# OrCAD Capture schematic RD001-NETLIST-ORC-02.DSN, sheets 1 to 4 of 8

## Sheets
1 8: size A3
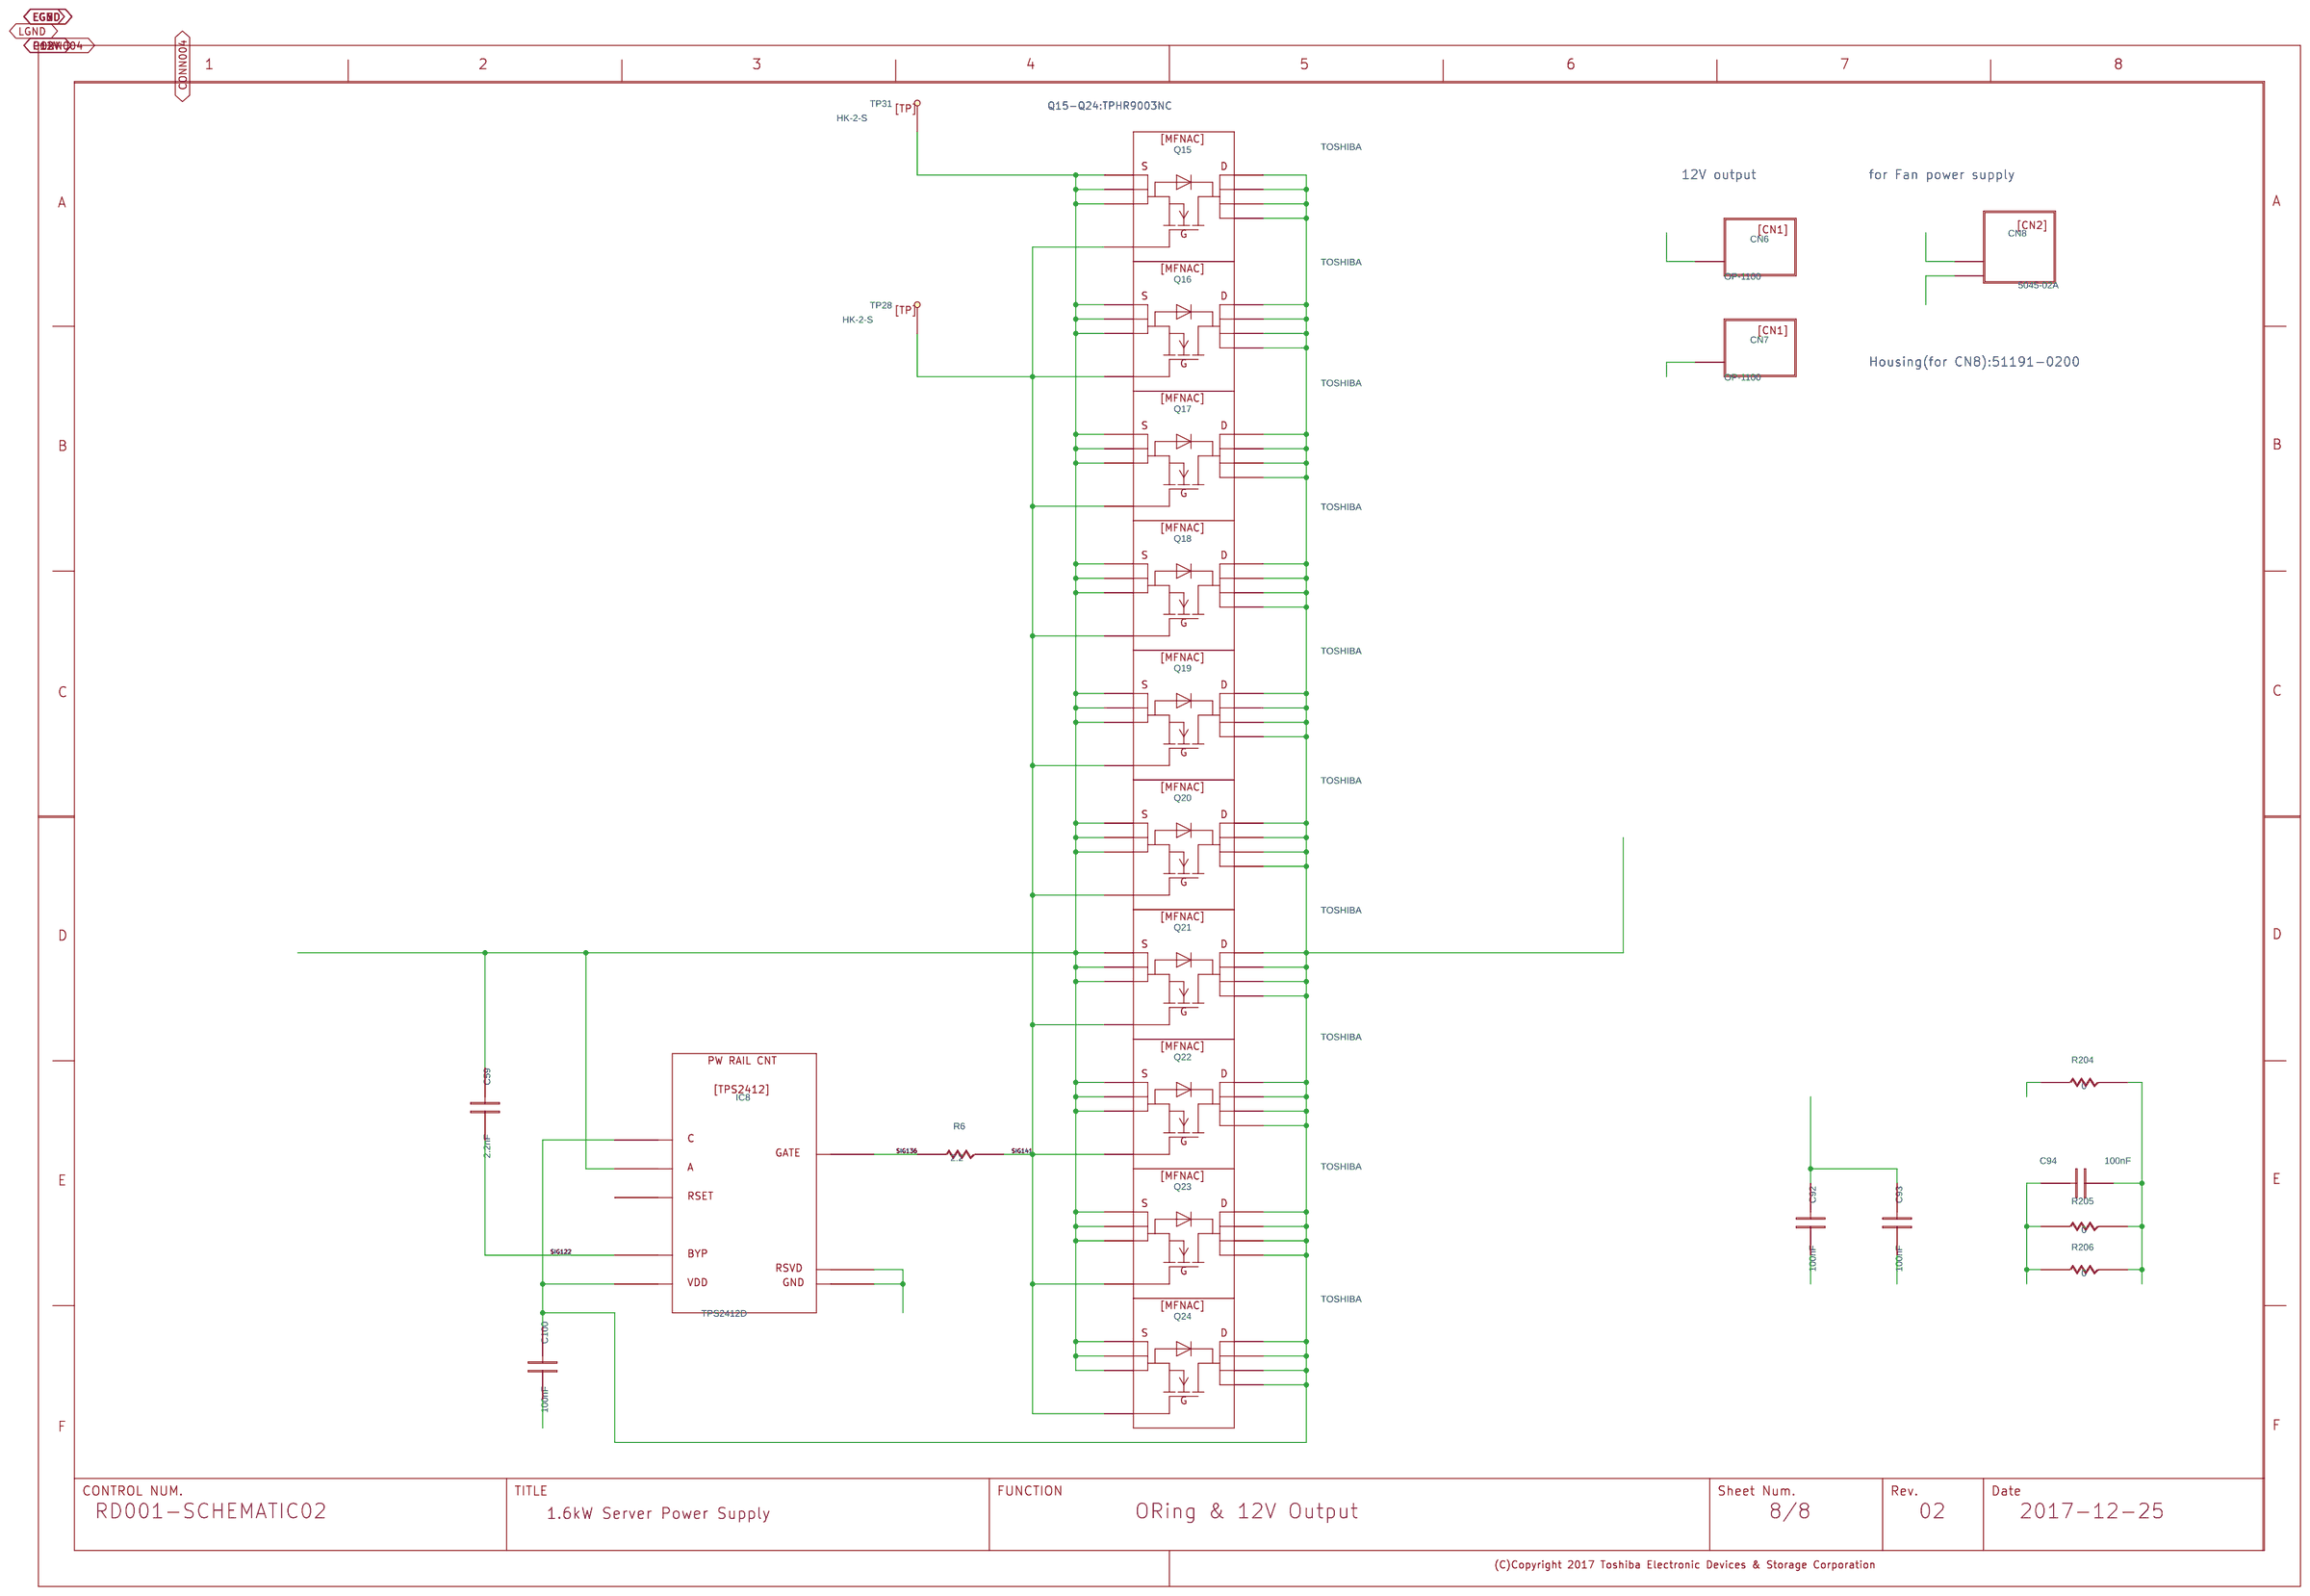
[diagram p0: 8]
2 7: size A3
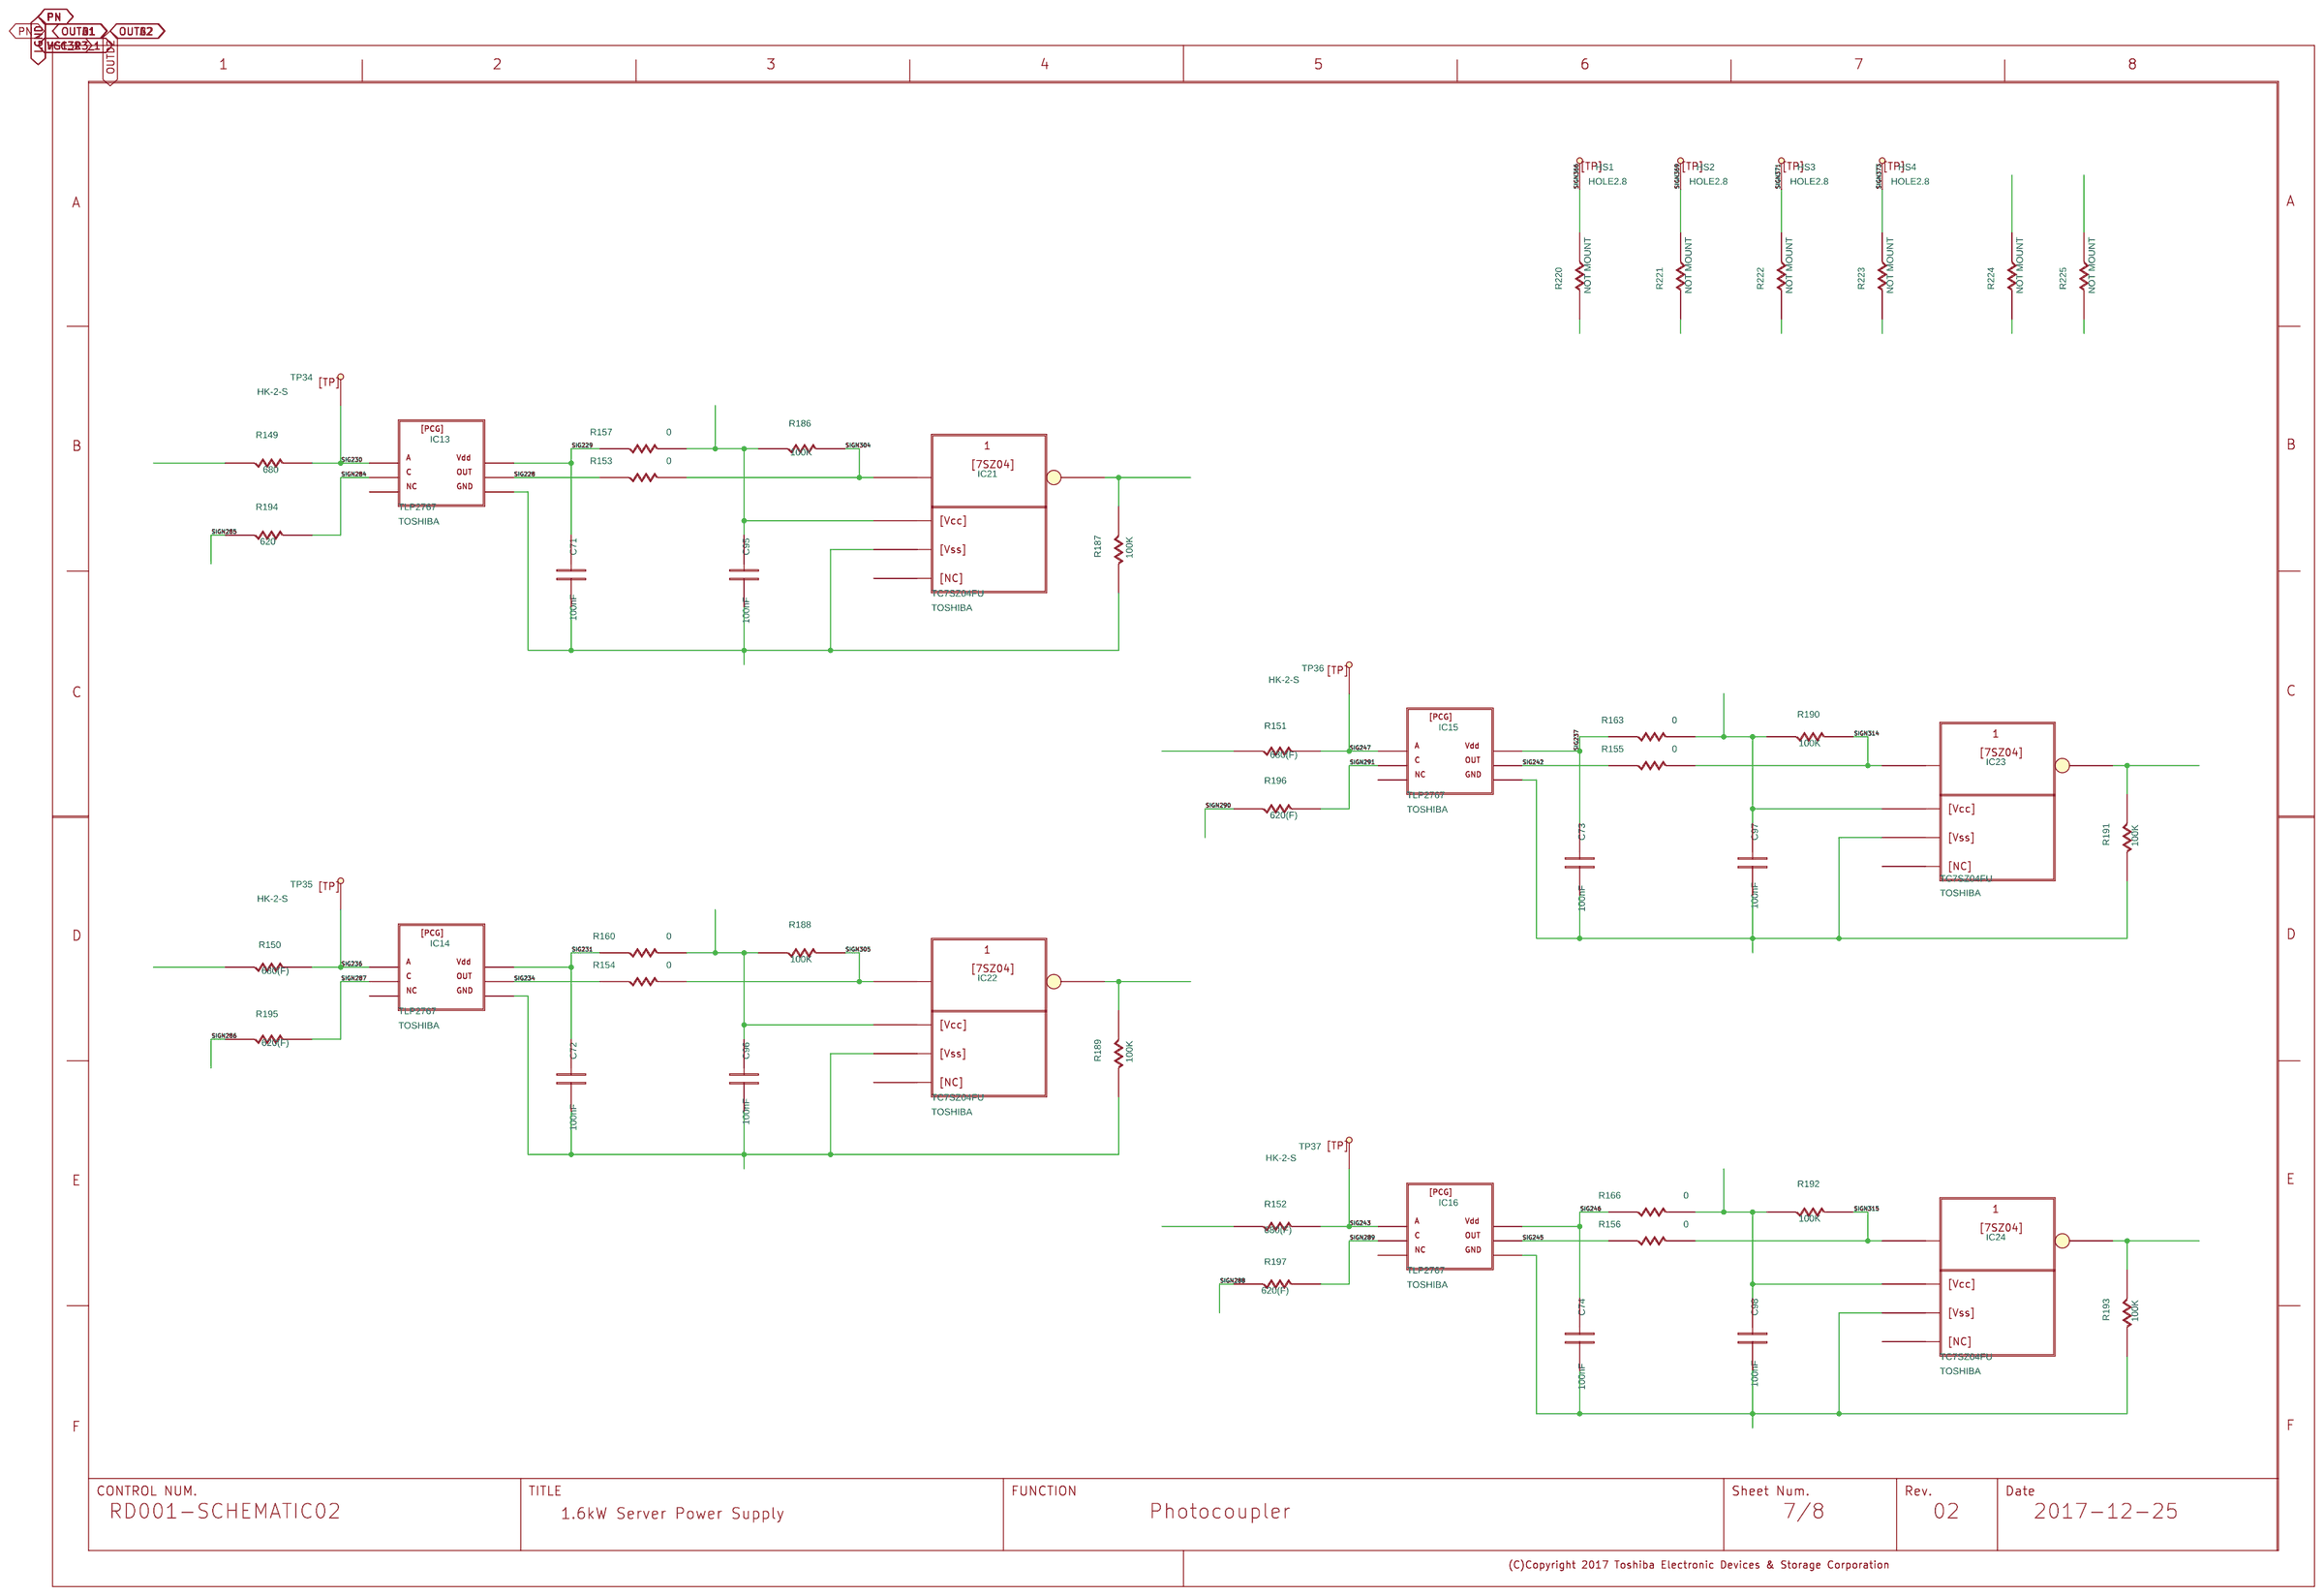
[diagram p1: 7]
3 6: size A3
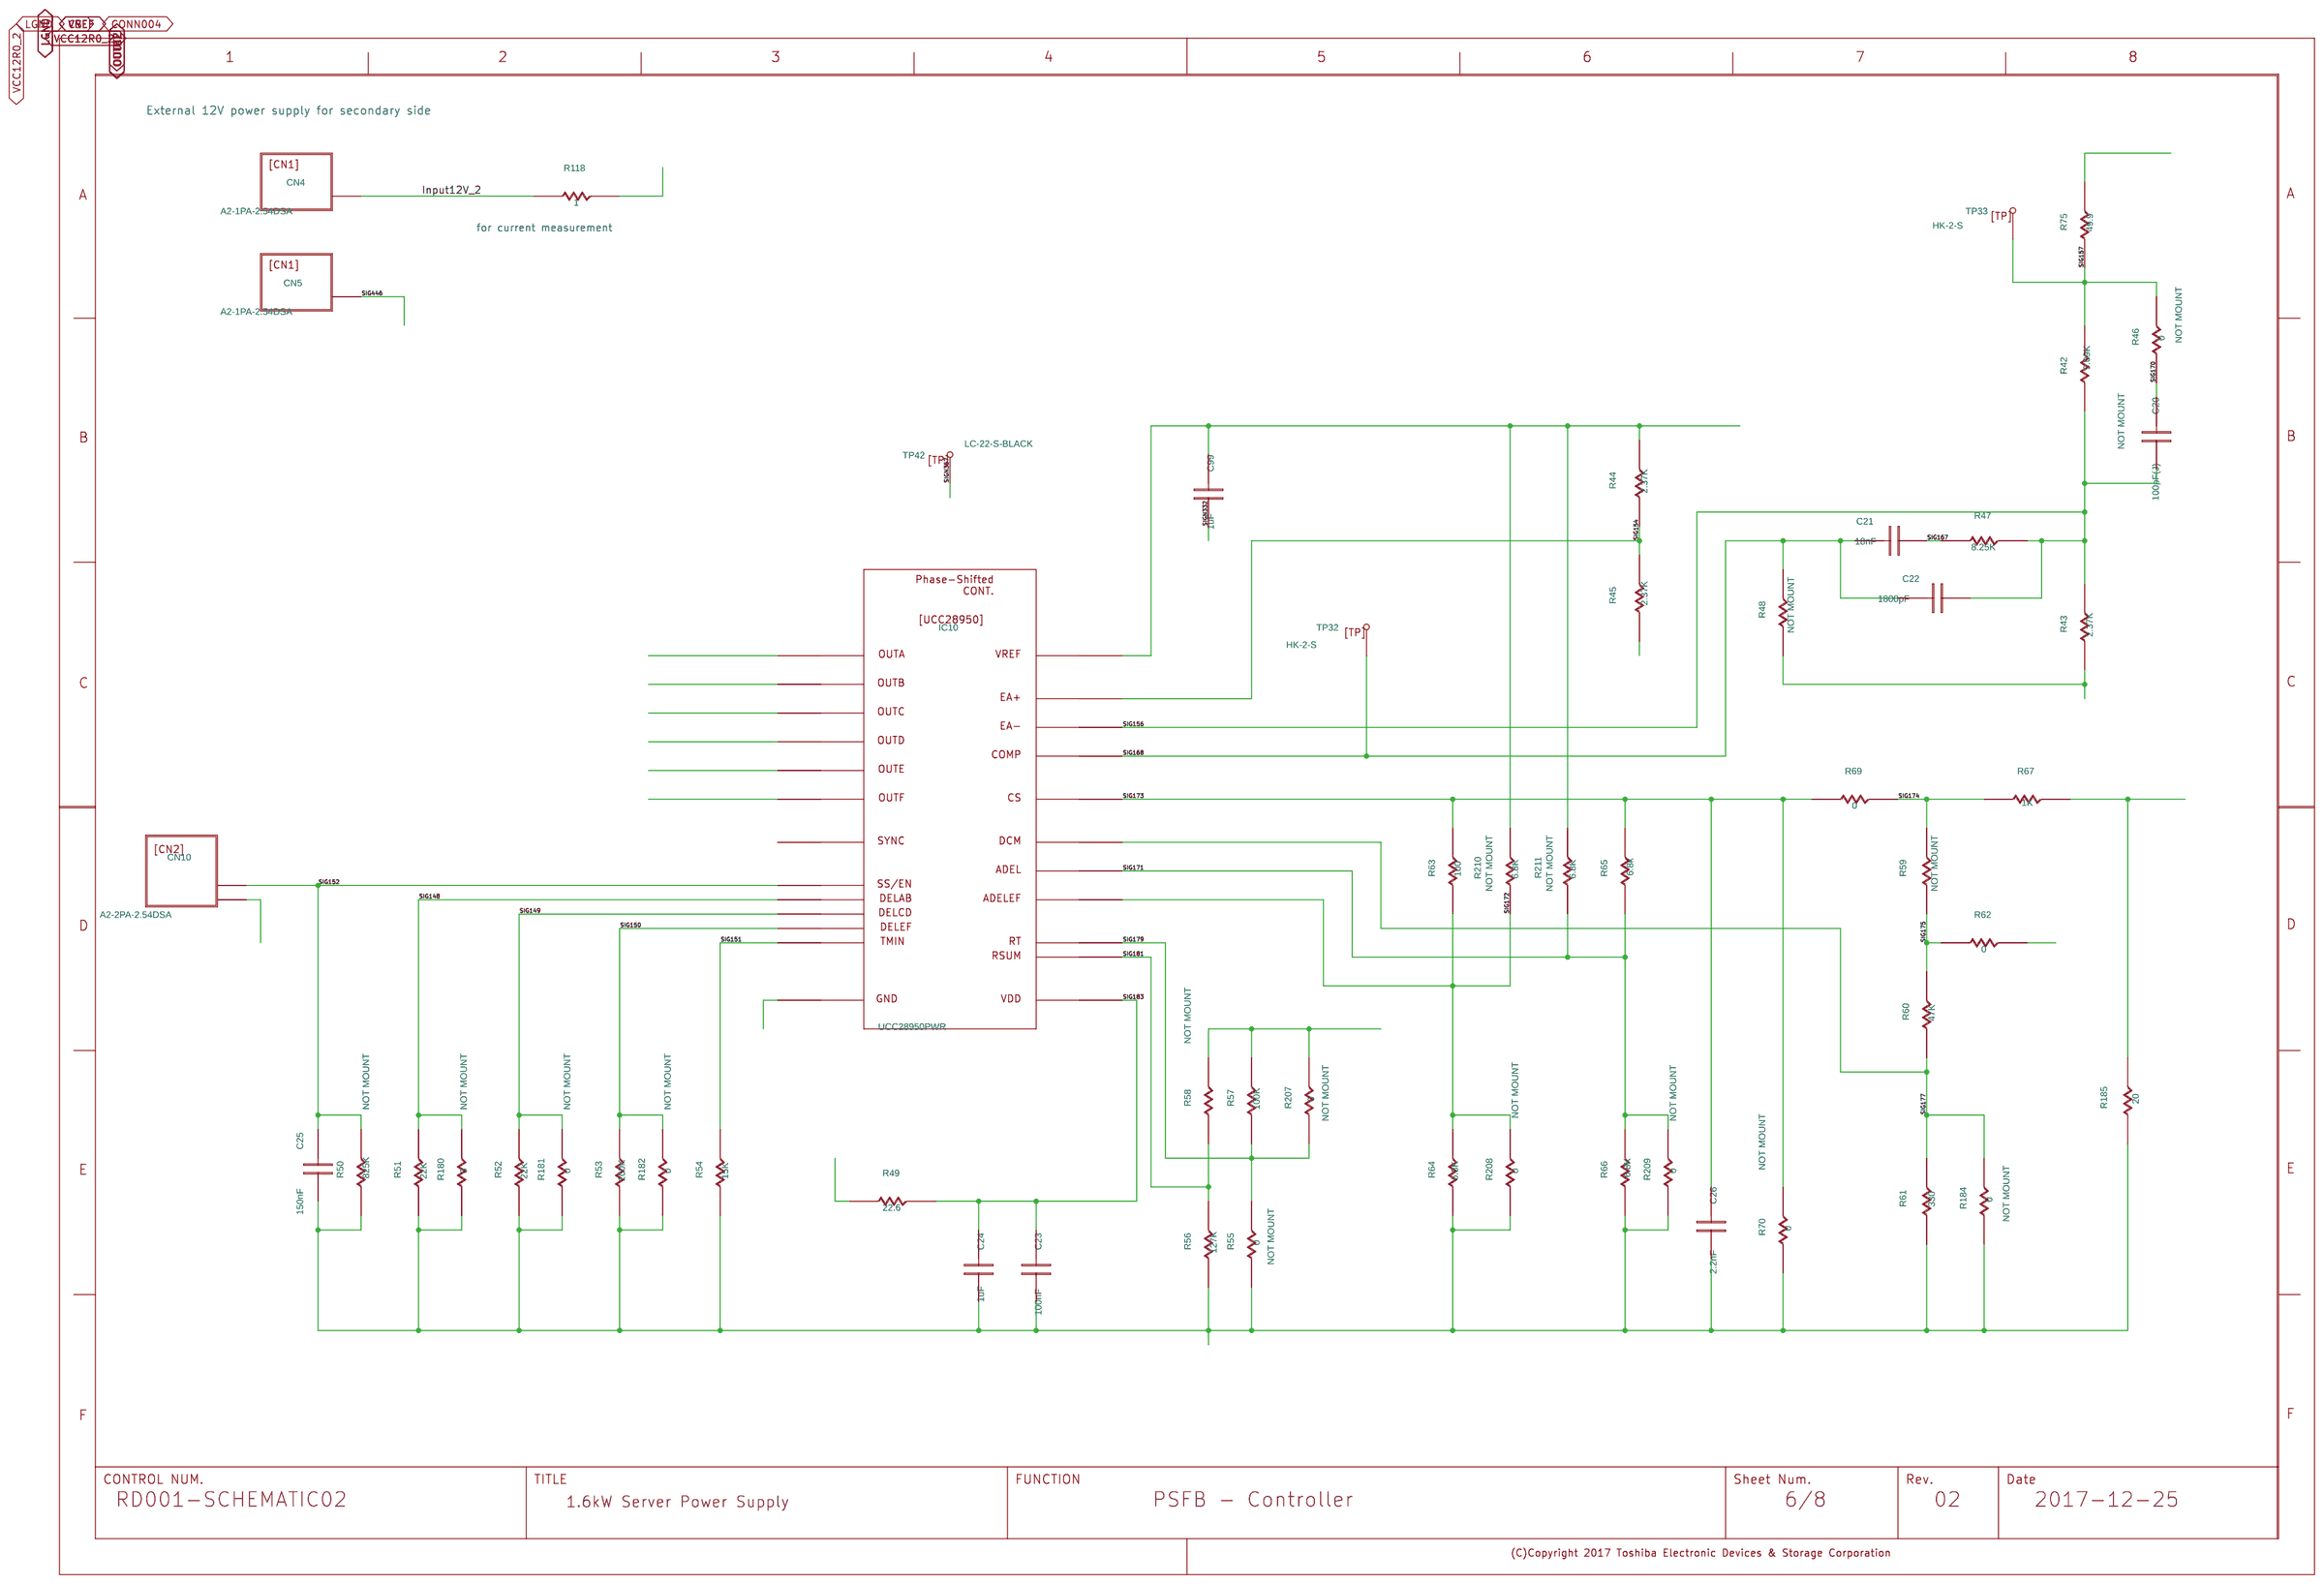
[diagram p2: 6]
4 5: size A3
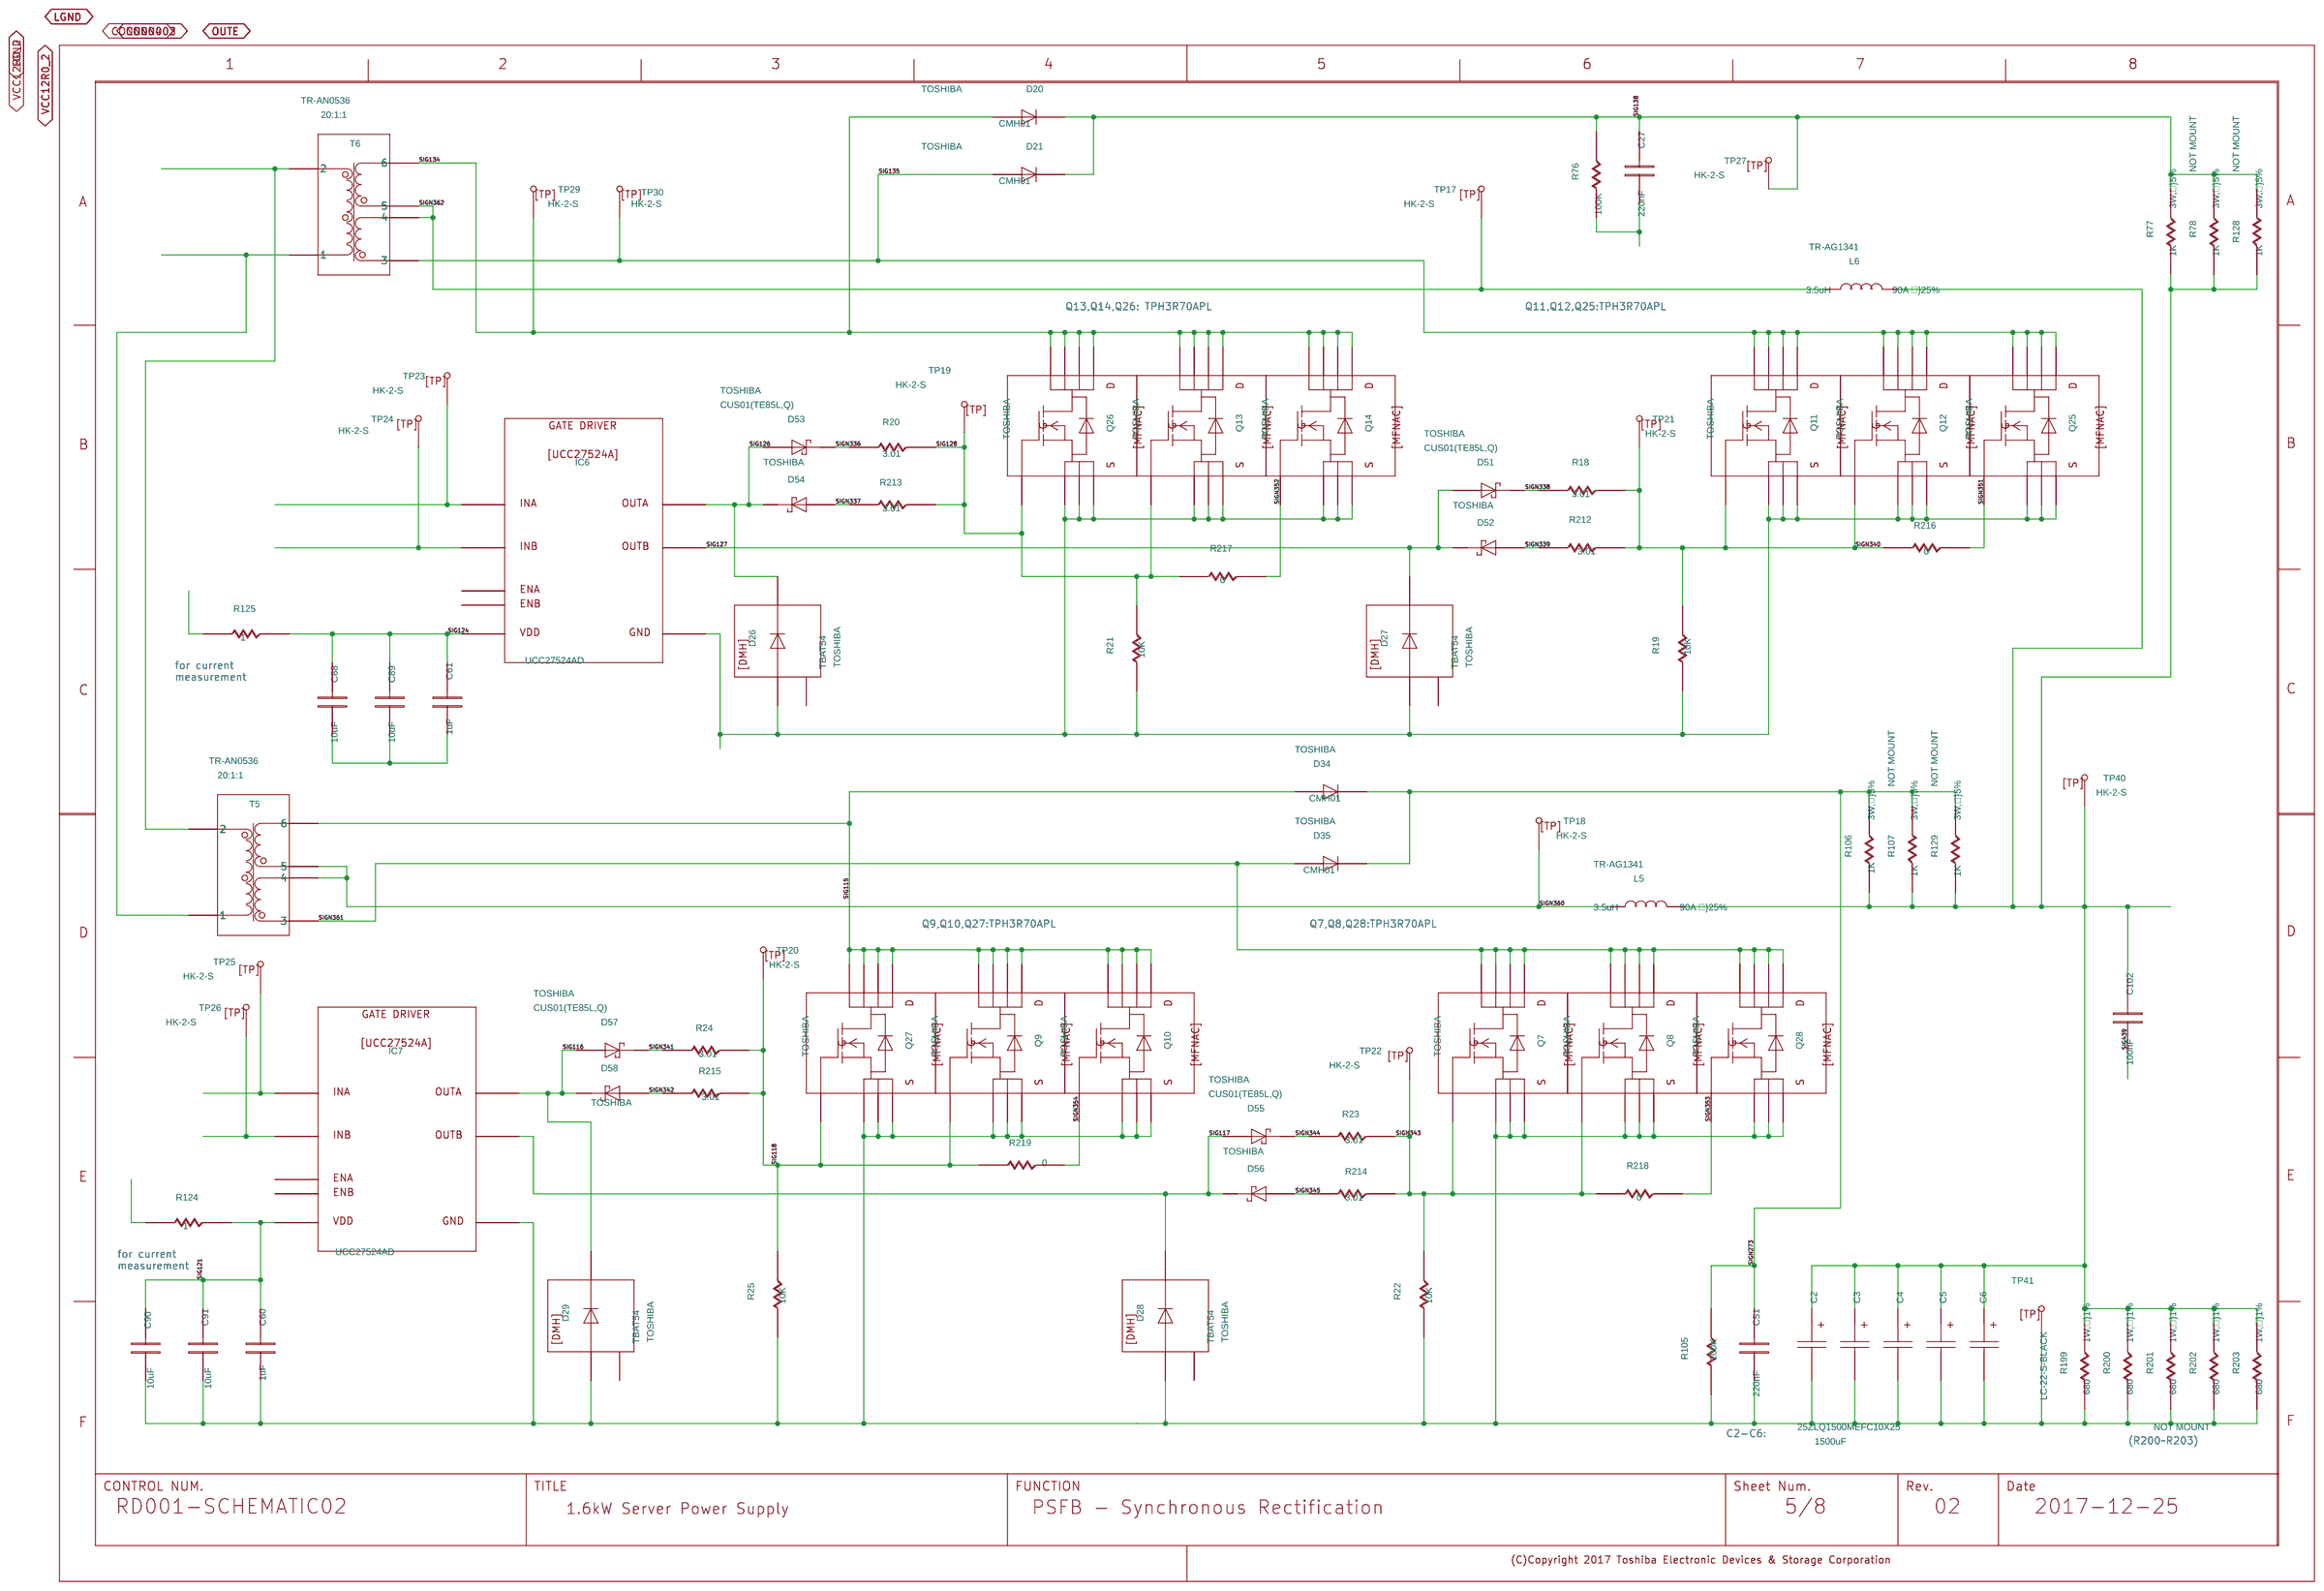
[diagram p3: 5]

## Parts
sheet 5
C2  CP
C3  CP
C4  CP
C5  CP
C6  CP
C27  C
C51  C
C60  C
C61  C
C88  C
C89  C
C90  C
C91  C
C102  C
D20  D
D21  D
D26  DMH
D27  DMH
D28  DMH
D29  DMH
D34  D
D35  D
D51  SBD
D52  SBD
D53  SBD
D54  SBD
D55  SBD
D56  SBD
D57  SBD
D58  SBD
IC6  L27524
IC7  L27524
L5  L
L6  L
Q7  MFNAC
Q8  MFNAC
Q9  MFNAC
Q10  MFNAC
Q11  MFNAC
Q12  MFNAC
Q13  MFNAC
Q14  MFNAC
Q25  MFNAC
Q26  MFNAC
Q27  MFNAC
Q28  MFNAC
R18  R
R19  R
R20  R
R21  R
R22  R
R23  R
R24  R
R25  R
R76  R
R77  R
R78  R
R105  R
R106  R
R107  R
R124  R
R125  R
R128  R
R129  R
R199  R
R200  R
R201  R
R202  R
R203  R
R212  R
R213  R
R214  R
R215  R
R216  R
R217  R
R218  R
R219  R
T5  T3_12V67A
T6  T3_12V67A
TP17  TP
TP18  TP
TP19  TP
TP20  TP
TP21  TP
TP22  TP
TP23  TP
TP24  TP
TP25  TP
TP26  TP
TP27  TP
TP29  TP
TP30  TP
TP40  TP
TP41  TP
U?#3  WAKU_DEF100
sheet 6
C20  C
C21  C
C22  C
C23  C
C24  C
C25  C
C26  C
C99  C
CN4  CN1
CN5  CN1
CN10  CN2
IC10  L28950
R42  R
R43  R
R44  R
R45  R
R46  R
R47  R
R48  R
R49  R
R50  R
R51  R
R52  R
R53  R
R54  R
R55  R
R56  R
R57  R
R58  R
R59  R
R60  R
R61  R
R62  R
R63  R
R64  R
R65  R
R66  R
R67  R
R69  R
R70  R
R75  R
R118  R
R180  R
R181  R
R182  R
R184  R
R185  R
R207  R
R208  R
R209  R
R210  R
R211  R
TP32  TP
TP33  TP
TP42  TP
U?#2  WAKU_DEF100
sheet 7
C71  C
C72  C
C73  C
C74  C
C95  C
C96  C
C97  C
C98  C
HS1  TP
HS2  TP
HS3  TP
HS4  TP
IC13  PCG6PIN
IC14  PCG6PIN
IC15  PCG6PIN
IC16  PCG6PIN
IC21  7SZ04
IC22  7SZ04
IC23  7SZ04
IC24  7SZ04
R149  R
R150  R
R151  R
R152  R
R153  R
R154  R
R155  R
R156  R
R157  R
R160  R
R163  R
R166  R
R186  R
R187  R
R188  R
R189  R
R190  R
R191  R
R192  R
R193  R
R194  R
R195  R
R196  R
R197  R
R220  R
R221  R
R222  R
R223  R
R224  R
R225  R
TP34  TP
TP35  TP
TP36  TP
TP37  TP
U?#1  WAKU_DEF100
sheet 8
C59  C
C92  C
C93  C
C94  C
C100  C
CN6  CN1
CN7  CN1
CN8  CN2
IC8  L2412
Q15  MFNAC
Q16  MFNAC
Q17  MFNAC
Q18  MFNAC
Q19  MFNAC
Q20  MFNAC
Q21  MFNAC
Q22  MFNAC
Q23  MFNAC
Q24  MFNAC
R6  R
R204  R
R205  R
R206  R
TP28  TP
TP31  TP
U?#8  WAKU_DEF100

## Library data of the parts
C2 = CP: CAPACITANCETOLE: M; CDMASTERCADCELG: DC0341; CHIPSIZE: D10xL22; COMP: PRT_3; COMPONENTTYPE: 4; FNLEADFREETHET1GT2GMCTH1: 0_2_N; GCOUNT: 1; MAKER: RUBYCON; MAXGCOUNT: 1; NOMINALCAPACITA: 56u; OUMECLASSIFICATION: ƒAƒ‹ƒ~“d‰ðƒRƒ“ƒfƒ“ƒT; OUMEPARTTYPE: C; PMPRODUCTSTYPEG: SV1; QUADMODEL: CON_56U; RATEDVOLTAGE: 16; SIZECODESMD: DIP; VAL1: 1500uF; VAL2: 25V,}20%; VAL3: 25ZLQ1500MEFC10X25
C3-C6 = CP: CAPACITANCETOLE: M; CHIPSIZE: D10xL22; COMP: PRT_3; COMPONENTTYPE: 4; GCOUNT: 1; MAKER: RUBYCON; MAXGCOUNT: 1; NOMINALCAPACITA: 56u; PMPRODUCTSTYPEG: SV1; RATEDVOLTAGE: 16; SIZECODESMD: DIP; VAL1: 1500uF; VAL2: 25V,}20%; VAL3: 25ZLQ1500MEFC10X25
C27 C51 = C: ADSMODELNAME: s_C1005JB1C224KT; CAPACITANCETOLE: K; CDMASTERCADCELG: KC0005; CHIPSIZE: 1005; COMP: PRT_52; COMPONENTTYPE: 4; FNLEADFREETHET1GT2GMCTH1: N_N_N; GCOUNT: 1; MAKER: TDK; MAXGCOUNT: 1; NOMINALCAPACITA: 220n; OUMECLASSIFICATION: ƒZƒ‰ƒ~ƒbƒNƒRƒ“ƒfƒ“ƒT; OUMEMAKER: TDK ‚s‚c‚j; OUMEMAKERKATAMEI: C1005JB1C224KT; QUADMODEL: CON_220N; RATEDVOLTAGE: 16; SIZECODESMD: 1005; TEMPCHARACTERI2: B; VAL1: 220nF; VAL2: 25V,}10%; VAL3: C1005X5R1E224K050BC
C24 C60 C61 C99 = C: ADSMODELNAME: s_GRM155B31E105KA12D; CAPACITANCETOLE: K; CDMASTERCADCELG: KC0005; CHIPSIZE: 1005; COMP: PRT_52; COMPONENTTYPE: 4; FNLEADFREETHET1GT2GMCTH1: 3_0_N; GCOUNT: 1; MAKER: TDK; MAXGCOUNT: 1; NOMINALCAPACITA: 1u; OUMECLASSIFICATION: ƒZƒ‰ƒ~ƒbƒNƒRƒ“ƒfƒ“ƒT; OUMEMAKER: MRT ºc»ì; OUMEMAKERKATAMEI: GRM155B31E105KA12D; PMPRODUCTSTYPEG: HD1; QUADMODEL: CON_1U; RATEDVOLTAGE: 25; SIZECODESMD: 1005; TEMPCHARACTERI2: B; VAL1: 1uF; VAL2: 25V,}20%; VAL3: C1005X5R1E105M050BC
C88-C91 = C: ADSMODELNAME: s_TMK316LD106KL_T; CAPACITANCETOLE: K; CDMASTERCADCELG: KC0014; CHIPSIZE: 3216; COMP: PRT_46; COMPONENTTYPE: 4; FNLEADFREETHET1GT2GMCTH1: N_N_N; GCOUNT: 1; MAKER: TAIYO YUDEN; MAXGCOUNT: 1; NOMINALCAPACITA: 10u; OUMECLASSIFICATION: ƒZƒ‰ƒ~ƒbƒNƒRƒ“ƒfƒ“ƒT; OUMEMAKER: TYD ‘¾—z—U“d; OUMEMAKERKATAMEI: TMK316LD106KL-T; QUADMODEL: CON_10U; RATEDVOLTAGE: 25; SIZECODESMD: 3216; VAL1: 10uF; VAL2: 25V,}10%; VAL3: TMK316BJ106KL-T
C23 C92-C94 C102 = C: ADSMODELNAME: s_GRM155R71E104KE14D; CAPACITANCETOLE: K; CDMASTERCADCELG: KC0005; CHIPSIZE: 1005; COMP: PRT_52; COMPONENTTYPE: 4; FNLEADFREETHET1GT2GMCTH1: N_N_N; GCOUNT: 1; MAKER: TDK; MAXGCOUNT: 1; NOMINALCAPACITA: 100n; OUMECLASSIFICATION: ƒZƒ‰ƒ~ƒbƒNƒRƒ“ƒfƒ“ƒT; OUMEMAKER: MRT ºc»ì; OUMEMAKERKATAMEI: GRM155R71E104KE14D; QUADMODEL: CON_100N; RATEDVOLTAGE: 25; SIZECODESMD: 1005; VAL1: 100nF; VAL2: 25V,}10%; VAL3: C1005X7R1E104K050BB
D20 D21 D34 D35 = D: ADSMODELNAME: s_MURS340T3G@@; CDMASTERCADCELG: KD0125; COMP: PRT_14; COMPONENTTYPE: 4; FNLEADFREETHET1GT2GMCTH1: N_N_N; FORWARDVOLTAGEM: 0; GCOUNT: 1; MAKER: TOSHIBA; MAXAVERAGEFORWA: 4; MAXGCOUNT: 1; MAXREPETITIVEPE: 400; MAXREVERSEVOLTA: 0; MOUNTINGFORMSMD: SMD; OUMECLASSIFICATION: êÊ®¬fq; OUMEMAKER: ONS IZ~R_N^[; OUMEMAKERKATAMEI: MURS340T3G@@; PEAKFORWARDVOLT: 1.28; PMPRODUCTSTYPEG: HEV; REVERSECURRENT: 250u; USERCOMPTEXT3: TOSHIBA; VAL3: CMH01; ZENERVOLTAGEMAX: 0; ZENERVOLTAGEMIN: 0
D26-D29 = DMH: COMP: PRT_25; COMPONENTTYPE: 4; MAKER: TOSHIBA; USERCOMPTEXT3: TOSHIBA; VAL3: TBAT54
D51-D58 = SBD: COMP: PRT_11; COMPONENTTYPE: 4; MAKER: TOSHIBA; USERCOMPTEXT3: TOSHIBA; VAL1: CUS01(TE85L,Q); VAL3: CUS01(TE85L,Q)
IC6 IC7 = L27524: COMP: PRT_63; COMPONENTTYPE: 4; MAKER: TEXAS; VAL3: UCC27524AD
L5 L6 = L: ADSMODELNAME: s_LPI_1R2D13; COMP: PRT_40; COMPONENTTYPE: 4; GCOUNT: 1; INDUCTANCEMAX: 0; INDUCTANCEMIN: 0; MAKER: TOKYO SEIDEN; MAXGCOUNT: 1; MOUNTINGFORMSMD: SMD; NOMINALINDUCTA1: 1.2u; NOMINALINDUCTA2: X; VAL1: 3.5uH; VAL2: 90A }25%; VAL3: TR-AG1341
Q7-Q14 Q25-Q28 = MFNAC: COMP: PRT_67; COMPONENTTYPE: 4; MAKER: TOSHIBA; USERCOMPTEXT3: TOSHIBA; VAL3: TPH3R70APL
R18 R20 R23 R24 R212-R215 = R: ADSMODELNAME: s_ERJ8GEYJ3R3V; CDMASTERCADCELG: KC0014; CHIPSIZE: 3216; COMP: PRT_5; COMPONENTTYPE: 4; FNLEADFREETHET1GT2GMCTH1: N_N_N; GCOUNT: 1; MAKER: VISHAY; MAXGCOUNT: 1; MOUNTINGFORMSMD: SMD; NOMINALRESISTAN: 3.3; OUMECLASSIFICATION: \ÊÀpÅèïRí; OUMEMAKER: NAE pi\jbNGNgjbNfoCX; OUMEMAKERKATAMEI: ERJ8GEYJ3R3V; POWERRATING: 250m; QUADMODEL: RES_3.3; RESISTANCETOLER: J; SIZECODESMD: 3216; VAL1: 3.01; VAL2: 500mW,}1%; VAL3: CRCW12063R01FKEAHP
R19 R21 R22 R25 = R: ADSMODELNAME: s_RK73B1JTTD103J@@; CDMASTERCADCELG: KC0133; CHIPSIZE: 1608; COMP: PRT_8; COMPONENTTYPE: 4; FNLEADFREETHET1GT2GMCTH1: N_N_N; GCOUNT: 1; MAKER: KOA; MAXGCOUNT: 1; MOUNTINGFORMSMD: SMD; NOMINALRESISTAN: 10K; OUMECLASSIFICATION: \ÊÀpÅèïRí; OUMEMAKER: KOA R[A; OUMEMAKERKATAMEI: RK73B1JTTD103J@@; POWERRATING: 100m; QUADMODEL: RES_10K; RESISTANCETOLER: J; SIZECODESMD: 1608; VAL1: 10K; VAL2: 100mW,}5%; VAL3: RK73B1JTTD103J
R76 R105 = R: ADSCOMPONENTNAME: R_3216; ADSMODELNAME: s_RK73H2BTTD1003F@@; CHIPSIZE: 3216; COMP: PRT_5; COMPONENTTYPE: 4; GCOUNT: 1; MAKER: PANASONIC; MAXGCOUNT: 1; MOUNTINGFORMSMD: SMD; PMPRODUCTSTYPEG: DA; SIZECODESMD: 3216; VAL1: 100K; VAL2: 250mW,}1%; VAL3: ERJ-8ENF1003V
R77 R106 = R: CDMASTERCADCELG: AXK0015; COMP: PRT_54; COMPONENTTYPE: 4; FNLEADFREETHET1GT2GMCTH1: N_N_N; GCOUNT: 1; MAKER: VISHAY; MAXGCOUNT: 1; MOUNTINGFORMSMD: DIP; NOMINALRESISTAN: 100; OUMECLASSIFICATION: _»à®çÅèïRí; OUMEMAKER: KOA R[A; OUMEMAKERKATAMEI: MOS3CT521A101J@@; PMPRODUCTSTYPEG: HEV; POWERRATING: 3; QUADMODEL: RES_100; RESISTANCETOLER: J; VAL1: 1K; VAL2: 3W,}5%; VAL3: PR03000201001JAC00
R78 R107 R128 R129 = R: CDMASTERCADCELG: AXK0015; COMP: PRT_54; COMPONENTTYPE: 4; FNLEADFREETHET1GT2GMCTH1: N_N_N; GCOUNT: 1; MAKER: VISHAY; MAXGCOUNT: 1; MOUNTINGFORMSMD: DIP; NOMINALRESISTAN: 100; NOTMOUNT: NOT MOUNT; OUMECLASSIFICATION: _»à®çÅèïRí; OUMEMAKER: KOA R[A; OUMEMAKERKATAMEI: MOS3CT521A101J@@; PMPRODUCTSTYPEG: HEV; POWERRATING: 3; QUADMODEL: RES_100; RESISTANCETOLER: J; VAL1: 1K; VAL2: 3W,}5%; VAL3: PR03000201001JAC00
R124 R125 = R: ADSMODELNAME: s_ERJ3GEYJ1R0V; CDMASTERCADCELG: KC0008; CHIPSIZE: 1608; COMP: PRT_8; COMPONENTTYPE: 4; FNLEADFREETHET1GT2GMCTH1: 2_1_N; GCOUNT: 1; MAKER: PANASONIC; MAXGCOUNT: 1; MOUNTINGFORMSMD: SMD; NOMINALRESISTAN: 1; OUMECLASSIFICATION: \ÊÀpÅèïRí; OUMEMAKER: NAE pi\jbNGNgjbNfoCX; OUMEMAKERKATAMEI: ERJ3GEYJ1R0V; PMPRODUCTSTYPEG: PC1; POWERRATING: 63m; QUADMODEL: RES_1; RESISTANCETOLER: J; SIZECODESMD: 1608; VAL1: 1; VAL2: 100mW,}5%; VAL3: ERJ-3GEYJ1R0V
R199 = R: CHIPSIZE: 6432; COMP: PRT_43; COMPONENTTYPE: 4; GCOUNT: 1; MAKER: VISHAY; MAXGCOUNT: 1; MOUNTINGFORMSMD: DIP; PMPRODUCTSTYPEG: HEV; VAL1: 680; VAL2: 1W,}1%; VAL3: CRCW2512680RFKEG
R200-R203 = R: CHIPSIZE: 6432; COMP: PRT_43; COMPONENTTYPE: 4; GCOUNT: 1; MAKER: VISHAY; MAXGCOUNT: 1; MOUNTINGFORMSMD: DIP; NOTMOUNT: NOT MOUNT; PMPRODUCTSTYPEG: HEV; VAL1: 680; VAL2: 1W,}1%; VAL3: CRCW2512680RFKEG
R216 = R: ADSCOMPONENTNAME: R_1608; ADSMODELNAME: s_SG73P1JTTD3R00F; CHIPSIZE: 1608; COMP: PRT_8; COMPONENTTYPE: 4; GCOUNT: 1; MAKER: KOA; MAXGCOUNT: 1; MOUNTINGFORMSMD: SMD; PMPRODUCTSTYPEG: DME; SIZECODESMD: 1608; VAL1: 0; VAL2: 100mW; VAL3: RK73Z1JTTD
R217-R219 = R: ADSMODELNAME: s_SG73P1JTTD3R00F; CHIPSIZE: 1608; COMP: PRT_8; COMPONENTTYPE: 4; GCOUNT: 1; MAKER: KOA; MAXGCOUNT: 1; MOUNTINGFORMSMD: SMD; PMPRODUCTSTYPEG: DME; SIZECODESMD: 1608; VAL1: 0; VAL2: 100mW; VAL3: RK73Z1JTTD
T5 T6 = T3_12V67A: COMP: PRT_55; COMPONENTTYPE: 4; VAL1: 20:1:1; VAL3: TR-AN0536
TP17-TP37 TP40 = TP: COMP: PRT_44; COMPONENTKIND: 111; COMPONENTTYPE: 4; MAKER: MAC8; VAL3: HK-2-S
TP41 TP42 = TP: COMP: PRT_34; COMPONENTKIND: 111; COMPONENTTYPE: 4; MAKER: MAC8; VAL3: LC-22-S-BLACK
U?#3 = WAKU_DEF100: COMPONENTTYPE: 2; DATE: 2017-12-25; DESIGNED: TOSHIBA; DRAWINGNUMBER: RD001-SCHEMATIC02; FUNCTION: PSFB - Synchronous Rectification; PAGENUMBER: 5; REVISION: 02; SAVEAREA0: -45080,-4508,463680,304612; SHEETNUMBER: 5/8; TIME: 12:01:09; TITLE: 1.6kW Server Power Supply; UPDATEDATE: 2017/12/25; UPDATETIME: 13:49:58; UPDATEUSER: f1043010
C20 = C: ADSMODELNAME: s_GRM188B11E104KA01D; CAPACITANCETOLE: K; CDMASTERCADCELG: KC0008; CHIPSIZE: 1608; COMP: PRT_48; COMPONENTTYPE: 4; FNLEADFREETHET1GT2GMCTH1: 3_1_N; GCOUNT: 1; MAXGCOUNT: 1; NOMINALCAPACITA: 100n; NOTMOUNT: NOT MOUNT; OUMECLASSIFICATION: ƒZƒ‰ƒ~ƒbƒNƒRƒ“ƒfƒ“ƒT; OUMEMAKER: MRT ºc»ì; OUMEMAKERKATAMEI: GRM188B11E104KA01D; PMPRODUCTSTYPEG: PC1; QUADMODEL: CON_100N; RATEDVOLTAGE: 25; SIZECODESMD: 1608; TEMPCHARACTERI2: B; VAL1: 100pF(J); VAL2: 50V,}5%
C21 = C: ADSCNVFLAG: ON; ADSCOMPONENTNAME: C_1005; ADSMODELNAME: s_GRM155B11E562KA01D; CAPACITANCETOLE: K; CDMASTERCADCELG: KC0005; CHIPSIZE: 1005; COMP: PRT_52; COMPONENTTYPE: 4; FNLEADFREETHET1GT2GMCTH1: 2_0_N; GCOUNT: 1; ICX_PART_MODEL: CON_5.6N; MAKER: MURATA; MAXGCOUNT: 1; NOMINALCAPACITA: 5.6n; OUMECLASSIFICATION: ƒZƒ‰ƒ~ƒbƒNƒRƒ“ƒfƒ“ƒT; OUMEMAKER: MRT ºc»ì; OUMEMAKERKATAMEI: GRM155B11E562KA01D; PMPRODUCTSTYPEG: HD1; QUADMODEL: CON_5.6N; RATEDVOLTAGE: 25; SIZECODESMD: 1005; SQ_PART_MODEL: CON_5.6N; TEMPCHARACTERI2: B; VAL1: 18nF; VAL2: 25V,}10%; VAL3: GRM155R71E183KA61D
C22 = C: ADSCNVFLAG: ON; ADSCOMPONENTNAME: C_1005; ADSMODELNAME: s_C1005JB1H561KT; CAPACITANCETOLE: K; CDMASTERCADCELG: KC0005; CHIPSIZE: 1005; COMP: PRT_52; COMPONENTTYPE: 4; FNLEADFREETHET1GT2GMCTH1: 2_0_N; GCOUNT: 1; ICX_PART_MODEL: CON_560P; MAKER: MURATA; MAXGCOUNT: 1; NOMINALCAPACITA: 560p; OUMECLASSIFICATION: ƒZƒ‰ƒ~ƒbƒNƒRƒ“ƒfƒ“ƒT; OUMEMAKER: TDK ‚s‚c‚j; OUMEMAKERKATAMEI: C1005JB1H561KT; PMPRODUCTSTYPEG: HD1-PC1; QUADMODEL: CON_560P; RATEDVOLTAGE: 50; SIZECODESMD: 1005; SQ_PART_MODEL: CON_560P; TEMPCHARACTERI2: B; VAL1: 1800pF; VAL2: 50V,}10%; VAL3: GRM155R71H182KA01D
C25 = C: ADSMODELNAME: s_C1005X5R1E154KT000E; CAPACITANCETOLE: K; CDMASTERCADCELG: KC0005; CHIPSIZE: 1005; COMP: PRT_52; COMPONENTTYPE: 4; FNLEADFREETHET1GT2GMCTH1: 3_0_N; GCOUNT: 1; MAKER: TDK; MAXGCOUNT: 1; NOMINALCAPACITA: 150n; OUMECLASSIFICATION: ƒZƒ‰ƒ~ƒbƒNƒRƒ“ƒfƒ“ƒT; OUMEMAKER: TDK ‚s‚c‚j; OUMEMAKERKATAMEI: C1005X5R1E154KT000E; PMPRODUCTSTYPEG: HD1; QUADMODEL: CON_150N; RATEDVOLTAGE: 25; SIZECODESMD: 1005; VAL1: 150nF; VAL2: 25V,}10%; VAL3: C1005JB1E154K050BC
C26 = C: ADSMODELNAME: s_UMK105BJ222KV_F; CAPACITANCETOLE: K; CDMASTERCADCELG: KC0005; CHIPSIZE: 1005; COMP: PRT_52; COMPONENTTYPE: 4; FNLEADFREETHET1GT2GMCTH1: 2_0_N; GCOUNT: 1; MAKER: TDK; MAXGCOUNT: 1; NOMINALCAPACITA: 2.2n; OUMECLASSIFICATION: ƒZƒ‰ƒ~ƒbƒNƒRƒ“ƒfƒ“ƒT; OUMEMAKER: TYD ‘¾—z—U“d; OUMEMAKERKATAMEI: UMK105BJ222KV-F; PMPRODUCTSTYPEG: HD1-PC1; QUADMODEL: CON_2.2N; RATEDVOLTAGE: 50; SIZECODESMD: 1005; TEMPCHARACTERI2: B; VAL1: 2.2nF; VAL2: 50V,}10%; VAL3: UMK105BJ222KV-F
CN4 CN5 = CN1: AUTHOR: user1; COMP: PRT_57; COMPONENTKIND: 135; COMPONENTTYPE: 4; DATE: 2004/01/19; MAKER: HIROSE; SAVEAREA0: -4590,-655,24652,18633; SAVECOUNT: 26; TIME: 13:28:28; UPDATEDATE: 2017/01/31; UPDATETIME: 10:27:25; UPDATEUSER: s.maruyama; VAL1: 3A; VAL2: 200V; VAL3: A2-1PA-2.54DSA
CN10 = CN2: COMP: PRT_56; COMPONENTTYPE: 4; MAKER: HIROSE; VAL3: A2-2PA-2.54DSA
IC10 = L28950: COMP: PRT_16; COMPONENTTYPE: 4; MAKER: TEXAS; VAL3: UCC28950PWR
R42 = R: ADSMODELNAME: s_RN73H1JTTD9091B10; CDMASTERCADCELG: KC0008; CHIPSIZE: 1608; COMP: PRT_8; COMPONENTTYPE: 4; FNLEADFREETHET1GT2GMCTH1: N_N_N; GCOUNT: 1; MAKER: PANASONIC; MAXGCOUNT: 1; MOUNTINGFORMSMD: SMD; NOMINALRESISTAN: 9.09K; OUMECLASSIFICATION: \ÊÀpÅèïRí; OUMEMAKER: KOA R[A; OUMEMAKERKATAMEI: RN73H1JTTD9091B10; PMPRODUCTSTYPEG: DME; POWERRATING: 100m; QUADMODEL: RES_9.09K; RESISTANCETOLER: B; SIZECODESMD: 1608; VAL1: 9.09K; VAL2: 100mW,}1%; VAL3: ERJ-3EKF9091V
R43-R45 = R: ADSMODELNAME: s_ERJ3EKF2201V@@; CDMASTERCADCELG: KC0165; CHIPSIZE: 1608; COMP: PRT_8; COMPONENTTYPE: 4; FNLEADFREETHET1GT2GMCTH1: 3_2_N; GCOUNT: 1; MAKER: PANASONIC; MAXGCOUNT: 1; MOUNTINGFORMSMD: SMD; NOMINALRESISTAN: 2.2K; OUMECLASSIFICATION: \ÊÀpÅèïRí; OUMEMAKER: NAE pi\jbNGNgjbNfoCX; OUMEMAKERKATAMEI: ERJ3EKF2201V@@; PMPRODUCTSTYPEG: DA; POWERRATING: 100m; QUADMODEL: RES_2.2K; RESISTANCETOLER: F; SIZECODESMD: 1608; VAL1: 2.37K; VAL2: 100mW,}1%; VAL3: ERJ-3EKF2371V
R46 = R: ADSMODELNAME: s_RN73H1JTTD9091B10; CDMASTERCADCELG: KC0008; CHIPSIZE: 1608; COMP: PRT_8; COMPONENTTYPE: 4; FNLEADFREETHET1GT2GMCTH1: N_N_N; GCOUNT: 1; MAKER: KOA; MAXGCOUNT: 1; MOUNTINGFORMSMD: SMD; NOMINALRESISTAN: 9.09K; NOTMOUNT: NOT MOUNT; OUMECLASSIFICATION: \ÊÀpÅèïRí; OUMEMAKER: KOA R[A; OUMEMAKERKATAMEI: RN73H1JTTD9091B10; PMPRODUCTSTYPEG: DME; POWERRATING: 100m; QUADMODEL: RES_9.09K; RESISTANCETOLER: B; SIZECODESMD: 1608; VAL1: 0; VAL2: 100mW; VAL3: RK73Z1JTTD
R47 = R: ADSMODELNAME: s_ERJ3EKF8251V; CDMASTERCADCELG: KC0167; CHIPSIZE: 1608; COMP: PRT_8; COMPONENTTYPE: 4; FNLEADFREETHET1GT2GMCTH1: N_N_N; GCOUNT: 1; MAKER: PANASONIC; MAXGCOUNT: 1; MOUNTINGFORMSMD: SMD; NOMINALRESISTAN: 8.25K; OUMECLASSIFICATION: \ÊÀpÅèïRí; OUMEMAKER: NAE pi\jbNGNgjbNfoCX; OUMEMAKERKATAMEI: ERJ3EKF8251V; POWERRATING: 100m; QUADMODEL: RES_8.25K; RESISTANCETOLER: F; SIZECODESMD: 1608; VAL1: 8.25K; VAL2: 100mW,}1%; VAL3: ERJ-3EKF8251V
R48 R55 R58 R59 R70 R180-R182 R184 R207-R209 = R: ADSMODELNAME: s_RK73Z1JTTD; CDMASTERCADCELG: KCK0203; CHIPSIZE: 1608; COMP: PRT_8; COMPONENTTYPE: 4; FNLEADFREETHET1GT2GMCTH1: 3_2_N; GCOUNT: 1; MAKER: KOA; MAXGCOUNT: 1; MOUNTINGFORMSMD: SMD; NOMINALRESISTAN: 0; NOTMOUNT: NOT MOUNT; OUMECLASSIFICATION: \ÊÀpÅèïRí; OUMEMAKER: KOA R[A; OUMEMAKERKATAMEI: RK73Z1JTTD; PMPRODUCTSTYPEG: DME-HD1-PC1; POWERRATING: 100m; QUADMODEL: RES_0; RESISTANCETOLER: X; SIZECODESMD: 1608; VAL1: 0; VAL2: 100mW; VAL3: RK73Z1JTTD
R49 = R: ADSMODELNAME: s_RK73B1JRTTD220J; CDMASTERCADCELG: KC0008; CHIPSIZE: 1608; COMP: PRT_8; COMPONENTTYPE: 4; FNLEADFREETHET1GT2GMCTH1: N_N_N; GCOUNT: 1; MAKER: PANASONIC; MAXGCOUNT: 1; MOUNTINGFORMSMD: SMD; NOMINALRESISTAN: 22; OUMECLASSIFICATION: \ÊÀpÅèïRí; OUMEMAKER: KOA R[A; OUMEMAKERKATAMEI: RK73B1JRTTD220J; POWERRATING: 100m; QUADMODEL: RES_22; RESISTANCETOLER: J; SIZECODESMD: 1608; VAL1: 22.6; VAL2: 100mW,}1%; VAL3: ERJ-3EKF22R6V
R50 = R: ADSCNVFLAG: ON; ADSCOMPONENTNAME: R_1608; ADSMODELNAME: s_MCR03EZHF8253; CDMASTERCADCELG: DR802R; CHIPSIZE: 1608; COMP: PRT_8; COMPONENTTYPE: 4; FNLEADFREETHET1GT2GMCTH1: 3_1_N; GCOUNT: 1; ICX_PART_MODEL: RES_825K; MAKER: PANASONIC; MAXGCOUNT: 1; MOUNTINGFORMSMD: SMD; NOMINALRESISTAN: 825K; NOTMOUNT: NOT MOUNT; OUMECLASSIFICATION: \ÊÀpÅèïRí; OUMEMAKER: ROH [; OUMEMAKERKATAMEI: MCR03EZHF8253; POWERRATING: 100m; QUADMODEL: RES_825K; RESISTANCETOLER: F; SIZECODESMD: 1608; SQ_PART_MODEL: RES_825K; VAL1: 825K; VAL2: 100mW,}1%; VAL3: ERJ-3EKF8253V
R51 R52 = R: ADSMODELNAME: s_RN73H1JTTD2202B10; CDMASTERCADCELG: KC0008; CHIPSIZE: 1608; COMP: PRT_8; COMPONENTTYPE: 4; FNLEADFREETHET1GT2GMCTH1: N_N_N; GCOUNT: 1; MAKER: PANASONIC; MAXGCOUNT: 1; MOUNTINGFORMSMD: SMD; NOMINALRESISTAN: 22K; OUMECLASSIFICATION: \ÊÀpÅèïRí; OUMEMAKER: KOA R[A; OUMEMAKERKATAMEI: RN73H1JTTD2202B10; POWERRATING: 100m; QUADMODEL: RES_22K; RESISTANCETOLER: B; SIZECODESMD: 1608; VAL1: 22K; VAL2: 100mW,}1%; VAL3: RK73H1JTTD2202F
R53 = R: ADSMODELNAME: s_RK73B1JTTD104G; CDMASTERCADCELG: KC0008; CHIPSIZE: 1608; COMP: PRT_8; COMPONENTTYPE: 4; FNLEADFREETHET1GT2GMCTH1: N_N_N; GCOUNT: 1; MAKER: KOA; MAXGCOUNT: 1; MOUNTINGFORMSMD: SMD; NOMINALRESISTAN: 100K; OUMECLASSIFICATION: \ÊÀpÅèïRí; OUMEMAKER: KOA R[A; OUMEMAKERKATAMEI: RK73B1JTTD104G; POWERRATING: 100m; QUADMODEL: RES_100K; RESISTANCETOLER: G; SIZECODESMD: 1608; VAL1: 100K; VAL2: 100mW,}5%; VAL3: RK73B1JTTD104J
R54 = R: ADSCNVFLAG: ON; ADSCOMPONENTNAME: R_1608; ADSMODELNAME: s_RK73H1JTTD1502F; CDMASTERCADCELG: KCK0203; CHIPSIZE: 1608; COMP: PRT_8; COMPONENTTYPE: 4; FNLEADFREETHET1GT2GMCTH1: 3_2_N; GCOUNT: 1; ICX_PART_MODEL: RES_15K; MAKER: KOA; MAXGCOUNT: 1; MOUNTINGFORMSMD: SMD; NOMINALRESISTAN: 15K; OUMECLASSIFICATION: \ÊÀpÅèïRí; OUMEMAKER: KOA R[A; OUMEMAKERKATAMEI: RK73H1JTTD1502F; PMPRODUCTSTYPEG: DME; POWERRATING: 100m; QUADMODEL: RES_15K; RESISTANCETOLER: F; SIZECODESMD: 1608; SQ_PART_MODEL: RES_15K; VAL1: 15K; VAL2: 100mW,}5%; VAL3: RK73B1JTTD153J
R56 = R: ADSMODELNAME: s_ERJ3EKF1203V; CDMASTERCADCELG: KC0008; CHIPSIZE: 1608; COMP: PRT_8; COMPONENTTYPE: 4; FNLEADFREETHET1GT2GMCTH1: N_N_N; GCOUNT: 1; MAKER: PANASONIC; MAXGCOUNT: 1; MOUNTINGFORMSMD: SMD; NOMINALRESISTAN: 120K; OUMECLASSIFICATION: \ÊÀpÅèïRí; OUMEMAKER: NAE pi\jbNGNgjbNfoCX; OUMEMAKERKATAMEI: ERJ3EKF1203V; POWERRATING: 100m; QUADMODEL: RES_120K; RESISTANCETOLER: F; SIZECODESMD: 1608; VAL1: 127K; VAL2: 100mW,}1%; VAL3: ERJ-3EKF1273V
R57 = R: ADSMODELNAME: s_ERJ3GEYJ104V; CDMASTERCADCELG: DR802R; CHIPSIZE: 1608; COMP: PRT_8; COMPONENTTYPE: 4; FNLEADFREETHET1GT2GMCTH1: 3_1_N; GCOUNT: 1; MAKER: PANASONIC; MAXGCOUNT: 1; MOUNTINGFORMSMD: SMD; NOMINALRESISTAN: 100K; OUMECLASSIFICATION: \ÊÀpÅèïRí; OUMEMAKER: NAE pi\jbNGNgjbNfoCX; OUMEMAKERKATAMEI: ERJ3GEYJ104V; POWERRATING: 63m; QUADMODEL: RES_100K; RESISTANCETOLER: J; SIZECODESMD: 1608; VAL1: 100K; VAL2: 100mW,}1%; VAL3: ERJ-3EKF1003V
R60 = R: ADSMODELNAME: s_RK73B1JTTD473G; CDMASTERCADCELG: KC0008; CHIPSIZE: 1608; COMP: PRT_8; COMPONENTTYPE: 4; FNLEADFREETHET1GT2GMCTH1: N_N_N; GCOUNT: 1; MAKER: KOA; MAXGCOUNT: 1; MOUNTINGFORMSMD: SMD; NOMINALRESISTAN: 47K; OUMECLASSIFICATION: \ÊÀpÅèïRí; OUMEMAKER: KOA R[A; OUMEMAKERKATAMEI: RK73B1JTTD473G; POWERRATING: 100m; QUADMODEL: RES_47K; RESISTANCETOLER: G; SIZECODESMD: 1608; VAL1: 47K; VAL2: 100mW,}5%; VAL3: RK73B1JTTD473J
R61 = R: ADSMODELNAME: s_RK73G1JTD331D; CDMASTERCADCELG: DR802R; CHIPSIZE: 1608; COMP: PRT_8; COMPONENTTYPE: 4; FNLEADFREETHET1GT2GMCTH1: 3_1_N; GCOUNT: 1; MAKER: KOA; MAXGCOUNT: 1; MOUNTINGFORMSMD: SMD; NOMINALRESISTAN: 330; OUMECLASSIFICATION: \ÊÀpÅèïRí; OUMEMAKER: KOA R[A; OUMEMAKERKATAMEI: RK73G1JTD331D; POWERRATING: 63m; QUADMODEL: RES_330; RESISTANCETOLER: D; SIZECODESMD: 1608; VAL1: 330; VAL2: 125mW,}5%; VAL3: RK73B1JTTD331J
R62 R204-R206 = R: ADSMODELNAME: s_RK73Z1JTTD; CDMASTERCADCELG: KCK0203; CHIPSIZE: 1608; COMP: PRT_8; COMPONENTTYPE: 4; FNLEADFREETHET1GT2GMCTH1: 3_2_N; GCOUNT: 1; MAKER: KOA; MAXGCOUNT: 1; MOUNTINGFORMSMD: SMD; NOMINALRESISTAN: 0; OUMECLASSIFICATION: \ÊÀpÅèïRí; OUMEMAKER: KOA R[A; OUMEMAKERKATAMEI: RK73Z1JTTD; PMPRODUCTSTYPEG: DME-HD1-PC1; POWERRATING: 100m; QUADMODEL: RES_0; RESISTANCETOLER: X; SIZECODESMD: 1608; VAL1: 0; VAL2: 100mW; VAL3: RK73Z1JTTD
R63 = R: ADSCOMPONENTNAME: R_1005; ADSMODELNAME: s_CR10_000V; CHIPSIZE: 1608; COMP: PRT_8; COMPONENTTYPE: 4; GCOUNT: 1; MAKER: KOA; MAXGCOUNT: 1; MOUNTINGFORMSMD: SMD; VAL1: 100; VAL2: 125mW,}5%; VAL3: RK73B1JTTD101J
R64 R66 = R: ADSMODELNAME: s_RN73H1JTTD6801B10; CDMASTERCADCELG: KCK0203; CHIPSIZE: 1608; COMP: PRT_8; COMPONENTTYPE: 4; FNLEADFREETHET1GT2GMCTH1: N_N_N; GCOUNT: 1; MAKER: KOA; MAXGCOUNT: 1; MOUNTINGFORMSMD: SMD; NOMINALRESISTAN: 6.8K; OUMECLASSIFICATION: \ÊÀpÅèïRí; OUMEMAKER: KOA R[A; OUMEMAKERKATAMEI: RN73H1JTTD6801B10; PMPRODUCTSTYPEG: DME; POWERRATING: 100m; QUADMODEL: RES_6.8K; RESISTANCETOLER: B; SIZECODESMD: 1608; VAL1: 6.8K; VAL2: 100mW,}5%; VAL3: RK73B1JTTD682J
R65 = R: ADSCOMPONENTNAME: R_1005; ADSMODELNAME: s_CR10_000V; CHIPSIZE: 1608; COMP: PRT_8; COMPONENTTYPE: 4; GCOUNT: 1; MAKER: KOA; MAXGCOUNT: 1; MOUNTINGFORMSMD: SMD; VAL1: 6.8k; VAL2: 100mW,}5%; VAL3: RK73B1JTTD682J
R67 = R: ADSMODELNAME: s_RN73H1JTTD1001B10; CDMASTERCADCELG: KC0008; CHIPSIZE: 1608; COMP: PRT_8; COMPONENTTYPE: 4; FNLEADFREETHET1GT2GMCTH1: N_N_N; GCOUNT: 1; MAKER: KOA; MAXGCOUNT: 1; MOUNTINGFORMSMD: SMD; NOMINALRESISTAN: 1K; OUMECLASSIFICATION: \ÊÀpÅèïRí; OUMEMAKER: KOA R[A; OUMEMAKERKATAMEI: RN73H1JTTD1001B10; POWERRATING: 100m; QUADMODEL: RES_1K; RESISTANCETOLER: B; SIZECODESMD: 1608; VAL1: 1K; VAL2: 125mW,}5%; VAL3: RK73B1JTTD102J
R69 = R: ADSCNVFLAG: ON; ADSCOMPONENTNAME: R_1608; ADSMODELNAME: s_RK73Z1JTTD; CDMASTERCADCELG: KCK0203; CHIPSIZE: 1608; COMP: PRT_8; COMPONENTTYPE: 4; FNLEADFREETHET1GT2GMCTH1: 3_2_N; GCOUNT: 1; ICX_PART_MODEL: RES_0; MAKER: KOA; MAXGCOUNT: 1; MOUNTINGFORMSMD: SMD; NOMINALRESISTAN: 0; OUMECLASSIFICATION: \ÊÀpÅèïRí; OUMEMAKER: KOA R[A; OUMEMAKERKATAMEI: RK73Z1JTTD; PMPRODUCTSTYPEG: DME-HD1-PC1; POWERRATING: 100m; QUADMODEL: RES_0; RESISTANCETOLER: X; SIZECODESMD: 1608; SQ_PART_MODEL: RES_0; VAL1: 0; VAL2: 100mW; VAL3: RK73Z1JTTD
R75 = R: ADSMODELNAME: s_RK73H1JTTD49R9D@@; CHIPSIZE: 1608; COMP: PRT_8; COMPONENTTYPE: 4; FNLEADFREETHET1GT2GMCTH1: N_N_N; GCOUNT: 1; MAKER: KOA; MAXGCOUNT: 1; MOUNTINGFORMSMD: SMD; NOMINALRESISTAN: 49.9; OUMECLASSIFICATION: \ÊÀpÅèïRí; OUMEMAKER: KOA R[A; OUMEMAKERKATAMEI: RK73H1JTTD49R9D@@; POWERRATING: 100m; QUADMODEL: RES_49.9; RESISTANCETOLER: D; SIZECODESMD: 1608; VAL1: 49.9; VAL2: 125mW,}1%; VAL3: RK73H1JTTD49R9F
R118 = R: ADSCNVFLAG: ON; ADSCOMPONENTNAME: R_1608; ADSMODELNAME: s_ERJ3GEYJ1R0V; CDMASTERCADCELG: KC0008; CHIPSIZE: 1608; COMP: PRT_8; COMPONENTTYPE: 4; FNLEADFREETHET1GT2GMCTH1: 2_1_N; GCOUNT: 1; ICX_PART_MODEL: RES_1; MAKER: PANASONIC; MAXGCOUNT: 1; MOUNTINGFORMSMD: SMD; NOMINALRESISTAN: 1; OUMECLASSIFICATION: \ÊÀpÅèïRí; OUMEMAKER: NAE pi\jbNGNgjbNfoCX; OUMEMAKERKATAMEI: ERJ3GEYJ1R0V; PMPRODUCTSTYPEG: PC1; POWERRATING: 63m; QUADMODEL: RES_1; RESISTANCETOLER: J; SIZECODESMD: 1608; SQ_PART_MODEL: RES_1; VAL1: 1; VAL2: 100mW,}5%; VAL3: ERJ-3GEYJ1R0V
R185 = R: ADSMODELNAME: s_MCR18EZHJ220; CDMASTERCADCELG: DR901A; CHIPSIZE: 3216; COMP: PRT_5; COMPONENTTYPE: 4; FNLEADFREETHET1GT2GMCTH1: N_N_N; GCOUNT: 1; MAKER: PANASONIC; MAXGCOUNT: 1; MOUNTINGFORMSMD: SMD; NOMINALRESISTAN: 22; OUMECLASSIFICATION: \ÊÀpÅèïRí; OUMEMAKER: ROH [; OUMEMAKERKATAMEI: MCR18EZHJ220; POWERRATING: 250m; QUADMODEL: RES_22; RESISTANCETOLER: J; SIZECODESMD: 3216; VAL1: 20; VAL2: 250mW,}5%; VAL3: ERJ-8GEYJ200V
R210 = R: ADSCOMPONENTNAME: R_1005; ADSMODELNAME: s_ERJ2RHD163X; CHIPSIZE: 1608; COMP: PRT_8; COMPONENTTYPE: 4; GCOUNT: 1; MAXGCOUNT: 1; MOUNTINGFORMSMD: SMD; NOTMOUNT: NOT MOUNT; PMPRODUCTSTYPEG: DME-HD1; VAL1: 6.8K; VAL2: 100mW,}5%; VAL3: RK73B1JTTD682J
R211 = R: ADSCOMPONENTNAME: R_1005; ADSMODELNAME: s_ERJ2RHD163X; CHIPSIZE: 1608; COMP: PRT_8; COMPONENTTYPE: 4; GCOUNT: 1; MAKER: KOA; MAXGCOUNT: 1; MOUNTINGFORMSMD: SMD; NOTMOUNT: NOT MOUNT; PMPRODUCTSTYPEG: DME-HD1; VAL1: 6.8K; VAL2: 100mW,}5%; VAL3: RK73B1JTTD682J
U?#2 = WAKU_DEF100: COMPONENTTYPE: 2; DATE: 2017-12-25; DESIGNED: TOSHIBA; DRAWINGNUMBER: RD001-SCHEMATIC02; FUNCTION: PSFB - Controller; PAGENUMBER: 6; REVISION: 02; SAVEAREA0: -45080,-4508,463680,304612; SHEETNUMBER: 6/8; TIME: 16:14:05; TITLE: 1.6kW Server Power Supply; UPDATEDATE: 2017/12/25; UPDATETIME: 13:49:58; UPDATEUSER: f1043010
C71-C74 = C: ADSCNVFLAG: ON; ADSCOMPONENTNAME: C_1005; ADSMODELNAME: s_GRM155R71E104KE14D; CAPACITANCETOLE: K; CDMASTERCADCELG: KC0005; CHIPSIZE: 1005; COMP: PRT_52; COMPONENTTYPE: 4; FNLEADFREETHET1GT2GMCTH1: N_N_N; GCOUNT: 1; ICX_PART_MODEL: CON_100N; MAKER: TDK; MAXGCOUNT: 1; NOMINALCAPACITA: 100n; OUMECLASSIFICATION: ƒZƒ‰ƒ~ƒbƒNƒRƒ“ƒfƒ“ƒT; OUMEMAKER: MRT ºc»ì; OUMEMAKERKATAMEI: GRM155R71E104KE14D; QUADMODEL: CON_100N; RATEDVOLTAGE: 25; SIZECODESMD: 1005; SQ_PART_MODEL: CON_100N; VAL1: 100nF; VAL2: 25V,}10%; VAL3: C1005X7R1E104K050BB
C95-C98 = C: ADSCOMPONENTNAME: C_1005; ADSMODELNAME: s_GRM155R71E104KE14D; CAPACITANCETOLE: K; CHIPSIZE: 1005; COMP: PRT_52; COMPONENTTYPE: 4; GCOUNT: 1; MAKER: TDK; MAXGCOUNT: 1; NOMINALCAPACITA: 100n; RATEDVOLTAGE: 25; SIZECODESMD: 1005; VAL1: 100nF; VAL2: 25V,}10%; VAL3: C1005X7R1E104K050BB
HS1-HS4 = TP: CHIPSIZE: Through Hole; COMP: PRT_39; COMPONENTKIND: 111; COMPONENTTYPE: 4; VAL3: HOLE2.8
IC13-IC16 = PCG6PIN: COMP: PRT_15; COMPONENTTYPE: 4; MAKER: TOSHIBA; USERCOMPTEXT3: TOSHIBA; VAL3: TLP2767
IC21-IC24 = 7SZ04: COMP: PRT_2; COMPONENTTYPE: 4; MAKER: TOSHIBA; USERCOMPTEXT3: TOSHIBA; VAL3: TC7SZ04FU
R149 = R: CHIPSIZE: 1608; COMP: PRT_8; COMPONENTTYPE: 4; MAKER: KOA; VAL1: 680; VAL2: 100mW,}1%; VAL3: RK73H1JTTD6800F
R150-R152 = R: CHIPSIZE: 1608; COMP: PRT_8; COMPONENTTYPE: 4; MAKER: KOA; VAL1: 680(F); VAL2: 100mW; VAL3: RK73H1JTTD6800F
R153-R157 R160 R163 R166 = R: ADSCNVFLAG: ON; ADSCOMPONENTNAME: R_1005; ADSMODELNAME: s_ERJ2GE0R00X; CDMASTERCADCELG: KC0005; CHIPSIZE: 1608; COMP: PRT_8; COMPONENTTYPE: 4; FNLEADFREETHET1GT2GMCTH1: 2_1_N; GCOUNT: 1; ICX_PART_MODEL: RES_0; MAKER: KOA; MAXGCOUNT: 1; MOUNTINGFORMSMD: SMD; NOMINALRESISTAN: 0; OUMECLASSIFICATION: \ÊÀpÅèïRí; OUMEMAKER: NAE pi\jbNGNgjbNfoCX; OUMEMAKERKATAMEI: ERJ2GE0R00X; PMPRODUCTSTYPEG: HD1-PC1; POWERRATING: 63m; QUADMODEL: RES_0; RESISTANCETOLER: X; SIZECODESMD: 1005; SQ_PART_MODEL: RES_0; VAL1: 0; VAL2: 100mW; VAL3: RK73Z1JTTD
R186-R193 = R: CHIPSIZE: 1608; COMP: PRT_8; COMPONENTTYPE: 4; MAKER: KOA; VAL1: 100K; VAL2: 100mW,}5%; VAL3: RK73B1JTTD104J
R194 = R: CHIPSIZE: 1608; COMP: PRT_8; COMPONENTTYPE: 4; MAKER: PANASONIC; VAL1: 620; VAL2: 100mW,}1%; VAL3: ERJ-3EKF6200V
R195-R197 = R: CHIPSIZE: 1608; COMP: PRT_8; COMPONENTTYPE: 4; MAKER: PANASONIC; VAL1: 620(F); VAL2: 100mW; VAL3: ERJ-3EKF6200V
R220-R225 = R: ADSCNVFLAG: ON; ADSCOMPONENTNAME: R_1005; ADSMODELNAME: s_CR10_000V; CDMASTERCADCELG: KC0005; CHIPSIZE: 1608; COMP: PRT_8; COMPONENTTYPE: 4; FNLEADFREETHET1GT2GMCTH1: N_N_N; GCOUNT: 1; ICX_PART_MODEL: RES_0; MAKER: KOA; MAXGCOUNT: 1; MOUNTINGFORMSMD: SMD; NOMINALRESISTAN: 0; NOTMOUNT: NOT MOUNT; OUMECLASSIFICATION: \ÊÀpÅèïRí; OUMEMAKER: HDK k¤dCHÆ; OUMEMAKERKATAMEI: CR10-000V; POWERRATING: 63m; QUADMODEL: RES_0; RESISTANCETOLER: X; SIZECODESMD: 1005; SQ_PART_MODEL: RES_0; VAL1: 0; VAL2: 100mW; VAL3: RK73Z1JTTD
U?#1 = WAKU_DEF100: COMPONENTTYPE: 2; DATE: 2017-12-25; DESIGNED: TOSHIBA; DRAWINGNUMBER: RD001-SCHEMATIC02; FUNCTION: Photocoupler; PAGENUMBER: 7; REVISION: 02; SAVEAREA0: -45080,-4508,463680,304612; SHEETNUMBER: 7/8; TIME: 18:12:27; TITLE: 1.6kW Server Power Supply; UPDATEDATE: 2017/12/25; UPDATETIME: 13:49:58; UPDATEUSER: f1043010
C59 = C: ADSCNVFLAG: ON; ADSCOMPONENTNAME: C_1005; ADSMODELNAME: s_UMK105BJ222KV_F; CAPACITANCETOLE: K; CDMASTERCADCELG: KC0005; CHIPSIZE: 1005; COMP: PRT_52; COMPONENTTYPE: 4; FNLEADFREETHET1GT2GMCTH1: 2_0_N; GCOUNT: 1; ICX_PART_MODEL: CON_2.2N; MAKER: TDK; MAXGCOUNT: 1; NOMINALCAPACITA: 2.2n; OUMECLASSIFICATION: ƒZƒ‰ƒ~ƒbƒNƒRƒ“ƒfƒ“ƒT; OUMEMAKER: TYD ‘¾—z—U“d; OUMEMAKERKATAMEI: UMK105BJ222KV-F; PMPRODUCTSTYPEG: HD1-PC1; QUADMODEL: CON_2.2N; RATEDVOLTAGE: 50; SIZECODESMD: 1005; SQ_PART_MODEL: CON_2.2N; TEMPCHARACTERI2: B; VAL1: 2.2nF; VAL2: 50V,}10%; VAL3: UMK105BJ222KV-F
C100 = C: ADSMODELNAME: s_GRM155R71H222KA01D; CAPACITANCETOLE: K; CDMASTERCADCELG: KC0005; CHIPSIZE: 1005; COMP: PRT_52; COMPONENTTYPE: 4; FNLEADFREETHET1GT2GMCTH1: 2_0_N; GCOUNT: 1; MAKER: TDK; MAXGCOUNT: 1; NOMINALCAPACITA: 2.2n; OUMECLASSIFICATION: ƒZƒ‰ƒ~ƒbƒNƒRƒ“ƒfƒ“ƒT; OUMEMAKER: MRT ºc»ì; OUMEMAKERKATAMEI: GRM155R71H222KA01D; PMPRODUCTSTYPEG: HD1; QUADMODEL: CON_2.2N; RATEDVOLTAGE: 50; SIZECODESMD: 1005; VAL1: 100nF; VAL2: 25V,}10%; VAL3: C1005X7R1E104K050BB
CN6 CN7 = CN1: COMP: PRT_38; COMPONENTTYPE: 4; MAKER: OSADA; VAL3: OP-1100
CN8 = CN2: COMP: PRT_42; COMPONENTTYPE: 4; MAKER: MOLEX; VAL3: 5045-02A
IC8 = L2412: COMP: PRT_62; COMPONENTTYPE: 4; MAKER: TEXAS; VAL3: TPS2412D
Q15-Q24 = MFNAC: COMP: PRT_60; COMPONENTTYPE: 4; MAKER: TOSHIBA; USERCOMPTEXT3: TOSHIBA; VAL3: TPHR9003NC
R6 = R: ADSMODELNAME: s_RC0603JR_072R2L; CDMASTERCADCELG: KC0008; CHIPSIZE: 1608; COMP: PRT_8; COMPONENTTYPE: 4; FNLEADFREETHET1GT2GMCTH1: 2_1_N; GCOUNT: 1; MAKER: KAMAYA; MAXGCOUNT: 1; MOUNTINGFORMSMD: SMD; NOMINALRESISTAN: 2.2; OUMECLASSIFICATION: \ÊÀpÅèïRí; OUMEMAKER: YGO ƒ„ƒQƒI; OUMEMAKERKATAMEI: RC0603JR-072R2L; PMPRODUCTSTYPEG: PC1; POWERRATING: 100m; QUADMODEL: RES_2.2; RESISTANCETOLER: J; SIZECODESMD: 1608; VAL1: 2.2; VAL2: 100mW,}5%; VAL3: RMC1/16 - 2R2J TP
U?#8 = WAKU_DEF100: COMPONENTTYPE: 2; DATE: 2017-12-25; DESIGNED: TOSHIBA; DRAWINGNUMBER: RD001-SCHEMATIC02; FUNCTION: ORing & 12V Output; PAGENUMBER: 8; REVISION: 02; SAVEAREA0: -45080,-4508,463680,304612; SHEETNUMBER: 8/8; TIME: 12:01:09; TITLE: 1.6kW Server Power Supply; UPDATEDATE: 2017/12/25; UPDATETIME: 13:49:58; UPDATEUSER: f1043010

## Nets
P12V: C92.2 C93.2 C100.2 CN6.1 IC8.1 IC8.6 Q15.5 Q15.6 Q15.7 Q15.8 Q16.5 Q16.6 Q16.7 Q16.8 Q17.5 Q17.6 Q17.7 Q17.8 Q18.5 Q18.6 Q18.7 Q18.8 Q19.5 Q19.6 Q19.7 Q19.8 Q20.5 Q20.6 Q20.7 Q20.8 Q21.5 Q21.6 Q21.7 Q21.8 Q22.5 Q22.6 Q22.7 Q22.8 Q23.5 Q23.6 Q23.7 Q23.8 Q24.5 Q24.6 Q24.7 Q24.8
VCC3R3_1: C95.2 C96.2 C97.2 C98.2 IC21.5 IC22.5 IC23.5 IC24.5 R157.1 R160.1 R163.1 R166.1 R186.2 R188.2 R190.2 R192.2 ; also on sheet 6
VCC12R0_2: R49.1 R118.2 R124.1 R125.1
CONN002: T5.1(2) T6.1(2) ; also on sheet 5
CONN003: T5.2(1) T6.2(1) ; also on sheet 5
CONN004: C2.2 C3.2 C4.2 C5.2 C6.2 C59.2 C102.2 CN8.1 IC8.7 L5.2 L6.2 Q15.1 Q15.2 Q15.3 Q16.1 Q16.2 Q16.3 Q17.1 Q17.2 Q17.3 Q18.1 Q18.2 Q18.3 Q19.1 Q19.2 Q19.3 Q20.1 Q20.2 Q20.3 Q21.1 Q21.2 Q21.3 Q22.1 Q22.2 Q22.3 Q23.1 Q23.2 Q23.3 Q24.1 Q24.2 Q24.3 R75.2 R77.1 R78.1 R106.1 R107.2 R128.2 R129.1 R199.2 R200.2 R201.2 R202.2 R203.2 TP31.1 TP40.1
CS: R67.2 R185.2 ; also on sheet 5
FG6: C93.1 C94.2 R205.1 R206.1
FG7: R204.1
HS1_1: R224.2
HS1_2: R225.2
Input12V_2: CN4.1 R118.1
LGND: C2.1 C3.1 C4.1 C5.1 C6.1 C23.1 C24.1 C25.1 C26.1 C27.1 C51.1 C60.1 C61.1 C88.1 C89.1 C90.1 C91.1 C92.1 C94.1 C99.1 C100.1 C102.1 CN5.1 CN7.1 CN8.2 CN10.2 D26.A D27.A D28.A D29.A IC6.3 IC7.3 IC8.3 IC8.4 IC10.24 Q7.1 Q7.2 Q7.3 Q8.1 Q8.2 Q8.3 Q9.1 Q9.2 Q9.3 Q10.1 Q10.2 Q10.3 Q11.1 Q11.2 Q11.3 Q12.1 Q12.2 Q12.3 Q13.1 Q13.2 Q13.3 Q14.1 Q14.2 Q14.3 Q25.1 Q25.2 Q25.3 Q26.1 Q26.2 Q26.3 Q27.1 Q27.2 Q27.3 Q28.1 Q28.2 Q28.3 R19.1 R21.1 R22.1 R25.1 R43.1 R45.1 R48.1 R50.1 R51.1 R52.1 R53.1 R54.1 R55.1 R56.1 R61.1 R64.1 R66.1 R70.1 R76.1 R105.1 R180.1 R181.1 R182.1 R184.1 R185.1 R194.2 R195.2 R196.2 R197.2 R199.1 R200.1 R201.1 R202.1 R203.1 R204.2 R205.2 R206.2 R208.1 R209.1 TP41.1 TP42.1 ; also on sheet 5
OUTA1: IC21.4 R187.2 ; also on sheet 5
OUTA2: IC10.22 R149.2
OUTB1: IC22.4 R189.2 ; also on sheet 5
OUTB2: IC10.21 R150.2
OUTC1: IC23.4 R191.2 ; also on sheet 5
OUTC2: IC10.20 R151.2
OUTD1: IC24.4 R193.2 ; also on sheet 5
OUTD2: IC10.19 R152.2
OUTE: IC6.2 IC7.2 IC10.18 TP23.1 TP25.1
OUTF: IC6.4 IC7.4 IC10.17 TP24.1 TP26.1
PN: C71.1 C72.1 C73.1 C74.1 C95.1 C96.1 C97.1 C98.1 IC13.4 IC14.4 IC15.4 IC16.4 IC21.3 IC22.3 IC23.3 IC24.3 R187.1 R189.1 R191.1 R193.1 R220.1 R221.1 R222.1 R223.1 R224.1 R225.1 ; also on sheet 5 6 7 8
SIG115: D34.A Q9.5 Q9.6 Q9.7 Q9.8 Q10.5 Q10.6 Q10.7 Q10.8 Q27.5 Q27.6 Q27.7 Q27.8 T5.5(6)
SIG116: D29.C D57.A D58.C IC7.7
SIG117: D28.C D55.A D56.C IC7.5
SIG118: Q9.4 Q27.4 R24.2 R25.2 R215.2 R219.1 TP20.1
SIG121: C60.2 C90.2 C91.2 IC7.6 R124.2
SIG122: C59.1 IC8.8
SIG124: C61.2 C88.2 C89.2 IC6.6 R125.2
SIG126: D26.C D53.A D54.C IC6.7
SIG127: D27.C D51.A D52.C IC6.5
SIG128: Q13.4 Q26.4 R20.2 R21.2 R213.2 R217.1 TP19.1
SIG134: D20.A Q13.5 Q13.6 Q13.7 Q13.8 Q14.5 Q14.6 Q14.7 Q14.8 Q26.5 Q26.6 Q26.7 Q26.8 T6.5(6) TP29.1
SIG135: D21.A Q11.5 Q11.6 Q11.7 Q11.8 Q12.5 Q12.6 Q12.7 Q12.8 Q25.5 Q25.6 Q25.7 Q25.8 T6.6(3) TP30.1
SIG136: IC8.5 R6.1
SIG138: C27.2 D20.C D21.C R76.2 R77.2 R78.2 R128.1 TP27.1
SIG141: Q15.4 Q16.4 Q17.4 Q18.4 Q19.4 Q20.4 Q21.4 Q22.4 Q23.4 Q24.4 R6.2 TP28.1
SIG148: IC10.6 R51.2 R180.2
SIG149: IC10.7 R52.2 R181.2
SIG150: IC10.8 R53.2 R182.2
SIG151: IC10.9 R54.2
SIG152: C25.2 CN10.1 IC10.5 R50.2
SIG154: IC10.2 R44.1 R45.2
SIG156: C20.1 C22.1 IC10.3 R42.1 R43.2 R47.2
SIG157: R42.2 R46.2 R75.1 TP33.1
SIG167: C21.1 R47.1
SIG168: C21.2 C22.2 IC10.4 R48.2 TP32.1
SIG170: C20.2 R46.1
SIG171: IC10.14 R65.1 R66.2 R209.2 R211.1
SIG172: IC10.13 R63.1 R64.2 R208.2 R210.1
SIG173: C26.2 IC10.15 R63.2 R65.2 R69.1 R70.2
SIG174: R59.2 R67.1 R69.2
SIG175: R59.1 R60.2 R62.1
SIG177: IC10.12 R60.1 R61.2 R184.2
SIG179: IC10.10 R55.2 R57.1 R207.1
SIG181: IC10.11 R56.2 R58.1
SIG183: C23.2 C24.2 IC10.23 R49.2
SIG228: IC13.5 R153.2
SIG229: C71.2 IC13.6 R157.2
SIG230: IC13.1 R149.1 TP34.1
SIG231: C72.2 IC14.6 R160.2
SIG234: IC14.5 R154.2
SIG236: IC14.1 R150.1 TP35.1
SIG237: C73.2 IC15.6 R163.2
SIG242: IC15.5 R155.2
SIG243: IC16.1 R152.1 TP37.1
SIG245: IC16.5 R156.2
SIG246: C74.2 IC16.6 R166.2
SIG247: IC15.1 R151.1 TP36.1
SIGN273: C51.2 D34.C D35.C R105.2 R106.2 R107.1 R129.2
SIGN284: IC13.3 R194.1
SIGN287: IC14.3 R195.1
SIGN289: IC16.3 R197.1
SIGN291: IC15.3 R196.1
SIGN304: IC21.2 R153.1 R186.1
SIGN305: IC22.2 R154.1 R188.1
SIGN314: IC23.2 R155.1 R190.1
SIGN315: IC24.2 R156.1 R192.1
SIGN336: D53.C R20.1
SIGN337: D54.A R213.1
SIGN338: D51.C R18.1
SIGN339: D52.A R212.1
SIGN340: Q11.4 Q12.4 R18.2 R19.2 R212.2 R216.1 TP21.1
SIGN341: D57.C R24.1
SIGN342: D58.A R215.1
SIGN343: Q7.4 Q8.4 R22.2 R23.2 R214.2 R218.1 TP22.1
SIGN344: D55.C R23.1
SIGN345: D56.A R214.1
SIGN351: Q25.4 R216.2
SIGN352: Q14.4 R217.2
SIGN353: Q28.4 R218.2
SIGN354: Q10.4 R219.2
SIGN360: L5.1 T5.3(4) T5.4(5) TP18.1
SIGN361: D35.A Q7.5 Q7.6 Q7.7 Q7.8 Q8.5 Q8.6 Q8.7 Q8.8 Q28.5 Q28.6 Q28.7 Q28.8 T5.6(3)
SIGN362: L6.1 T6.3(4) T6.4(5) TP17.1
SIGN366: HS1.1 R220.2
SIGN369: HS2.1 R221.2
SIGN371: HS3.1 R222.2
SIGN373: HS4.1 R223.2
VREF: C99.2 IC10.1 R44.2 R57.2 R58.2 R62.2 R207.2 R210.2 R211.2

Not connected (* = marked no-connect by the designer): D26 NC; D27 NC; D28 NC; D29 NC; IC6 1 8; IC7 1 8; IC8 2; IC10 16; IC13 2; IC14 2; IC15 2; IC16 2; IC21 1; IC22 1; IC23 1; IC24 1

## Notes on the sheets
sheet 1
- Q15-Q24:TPHR9003NC
- 12V output
- for Fan power supply
- Housing(for CN8):51191-0200
sheet 3
- External 12V power supply for secondary side
- for current measurement
sheet 4
- Q13,Q14,Q26: TPH3R70APL
- Q11,Q12,Q25:TPH3R70APL
- for current
  measurement
- Q9,Q10,Q27:TPH3R70APL
- Q7,Q8,Q28:TPH3R70APL
- for current
  measurement
- C2-C6:
- (R200~R203)
